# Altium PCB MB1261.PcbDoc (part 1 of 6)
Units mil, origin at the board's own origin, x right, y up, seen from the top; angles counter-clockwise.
Board outline 5119.1 x 2638.79 mil, 6 copper layers (TOP, L2_GND, L3_SIG, L4_VCC, L5_GND, BOTTOM), stack 61 mil thick; 336 components, 316 nets, 1358 pads, 871 vias.
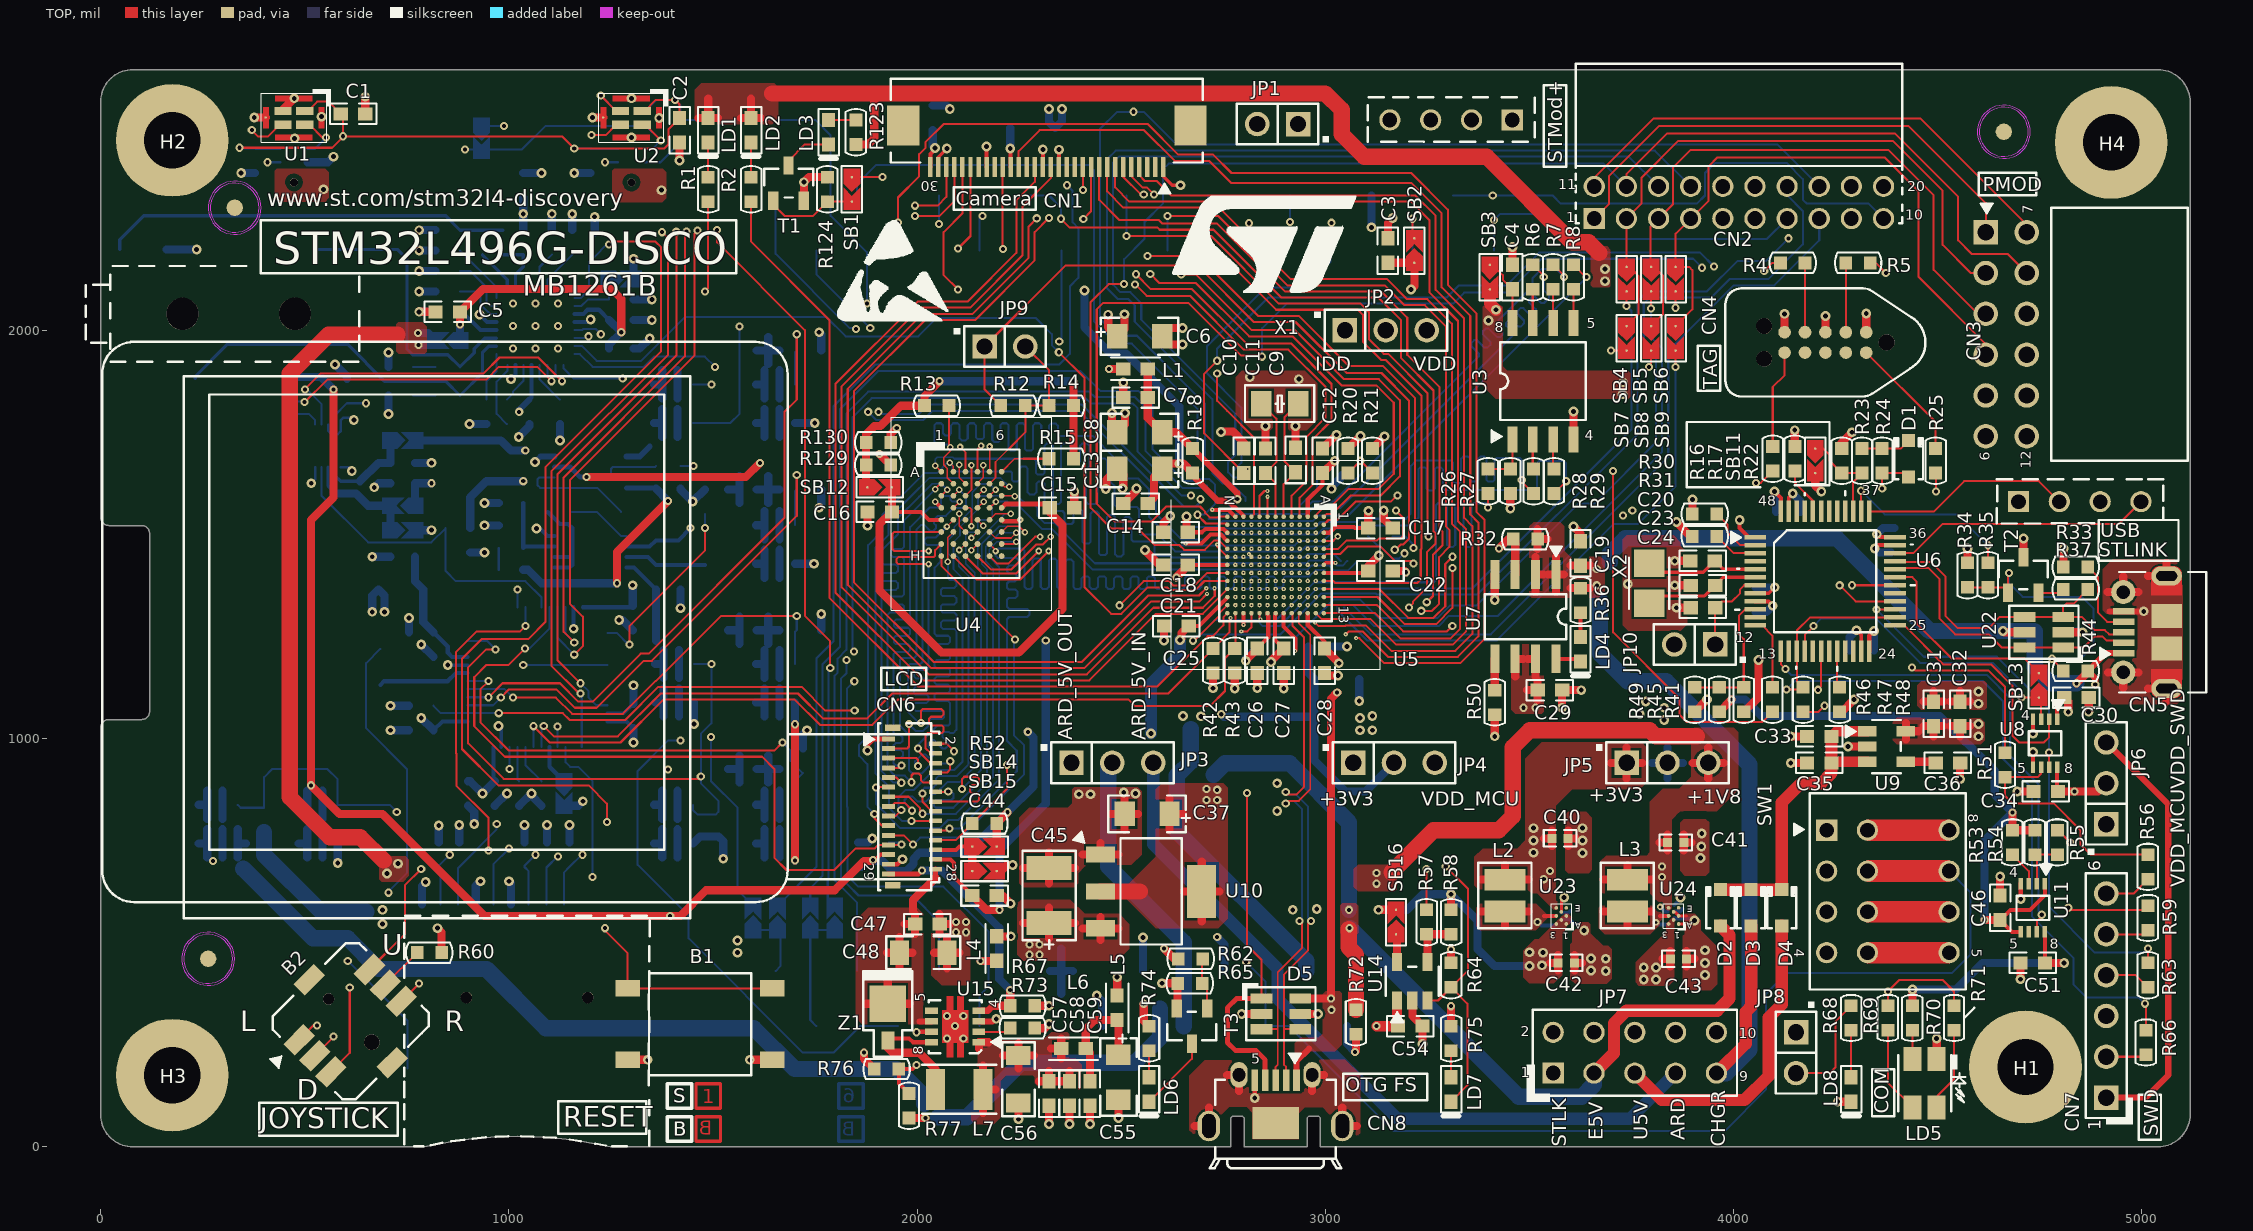
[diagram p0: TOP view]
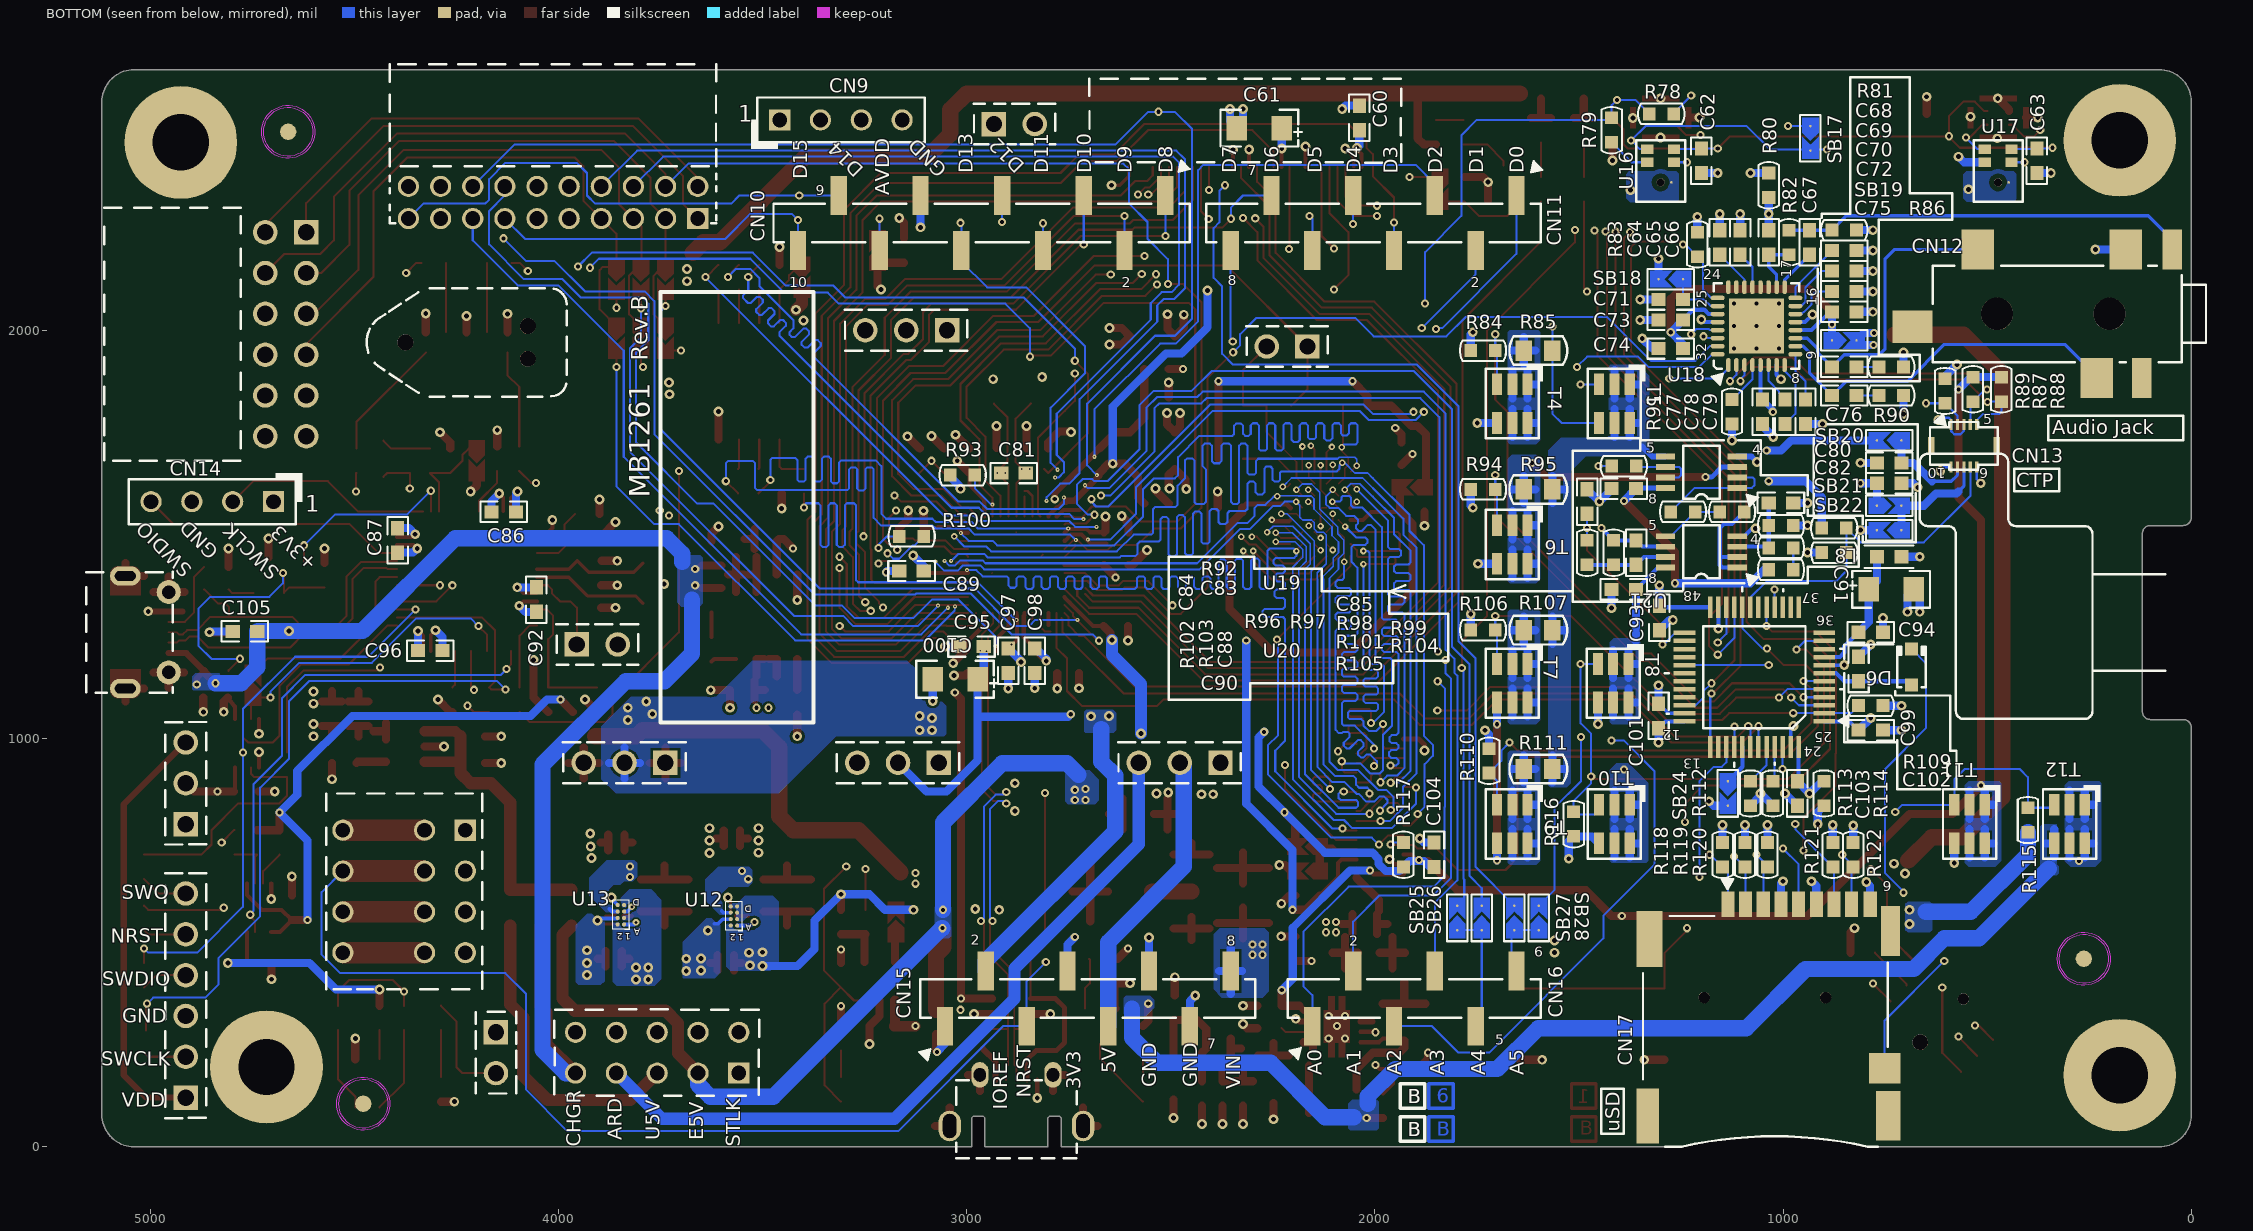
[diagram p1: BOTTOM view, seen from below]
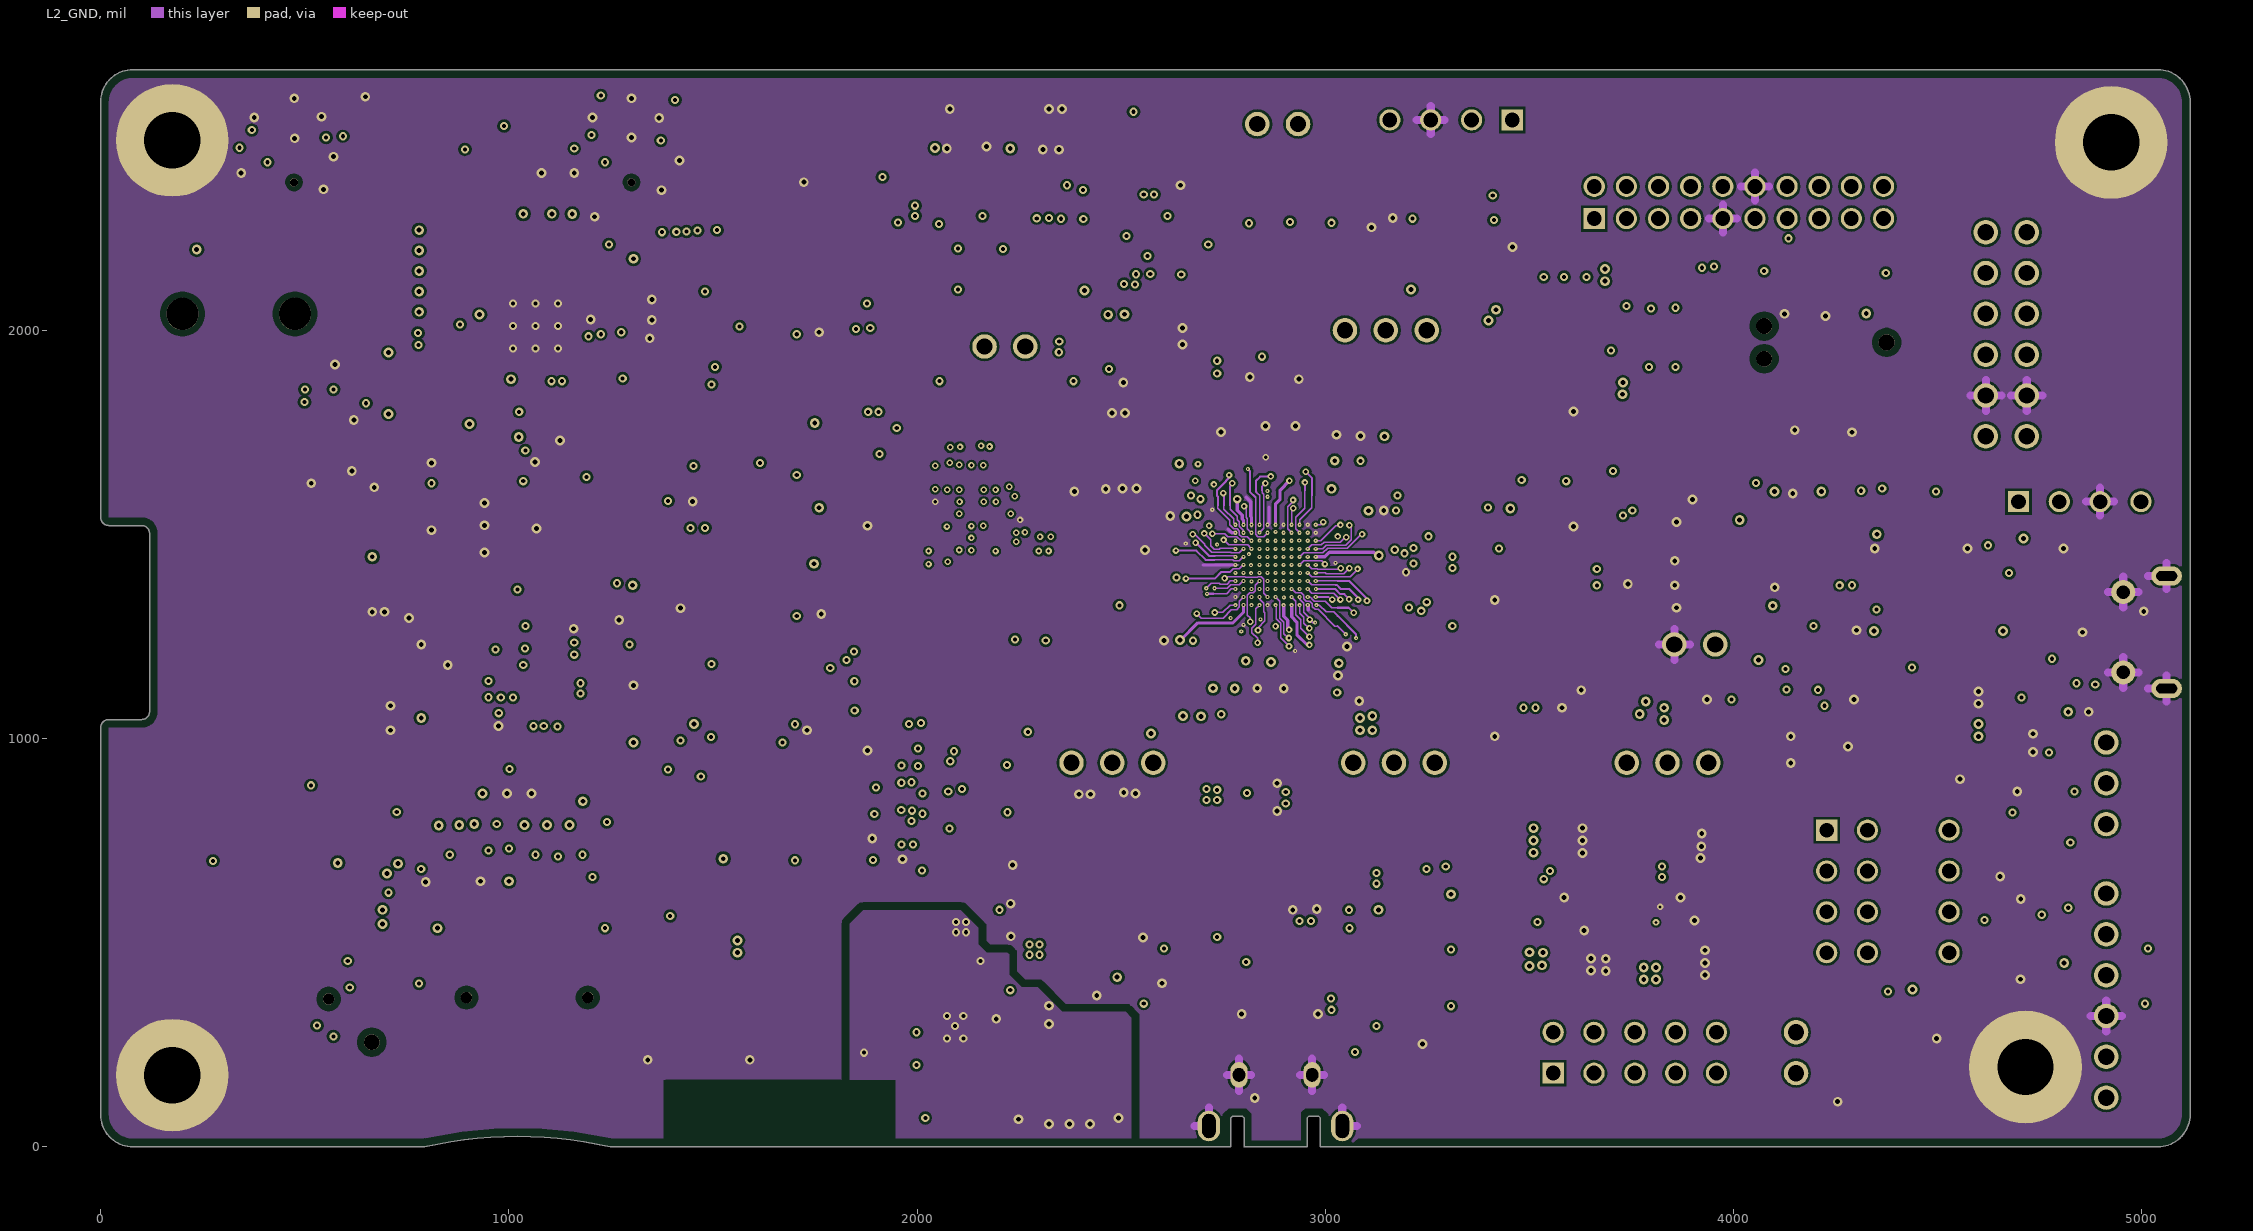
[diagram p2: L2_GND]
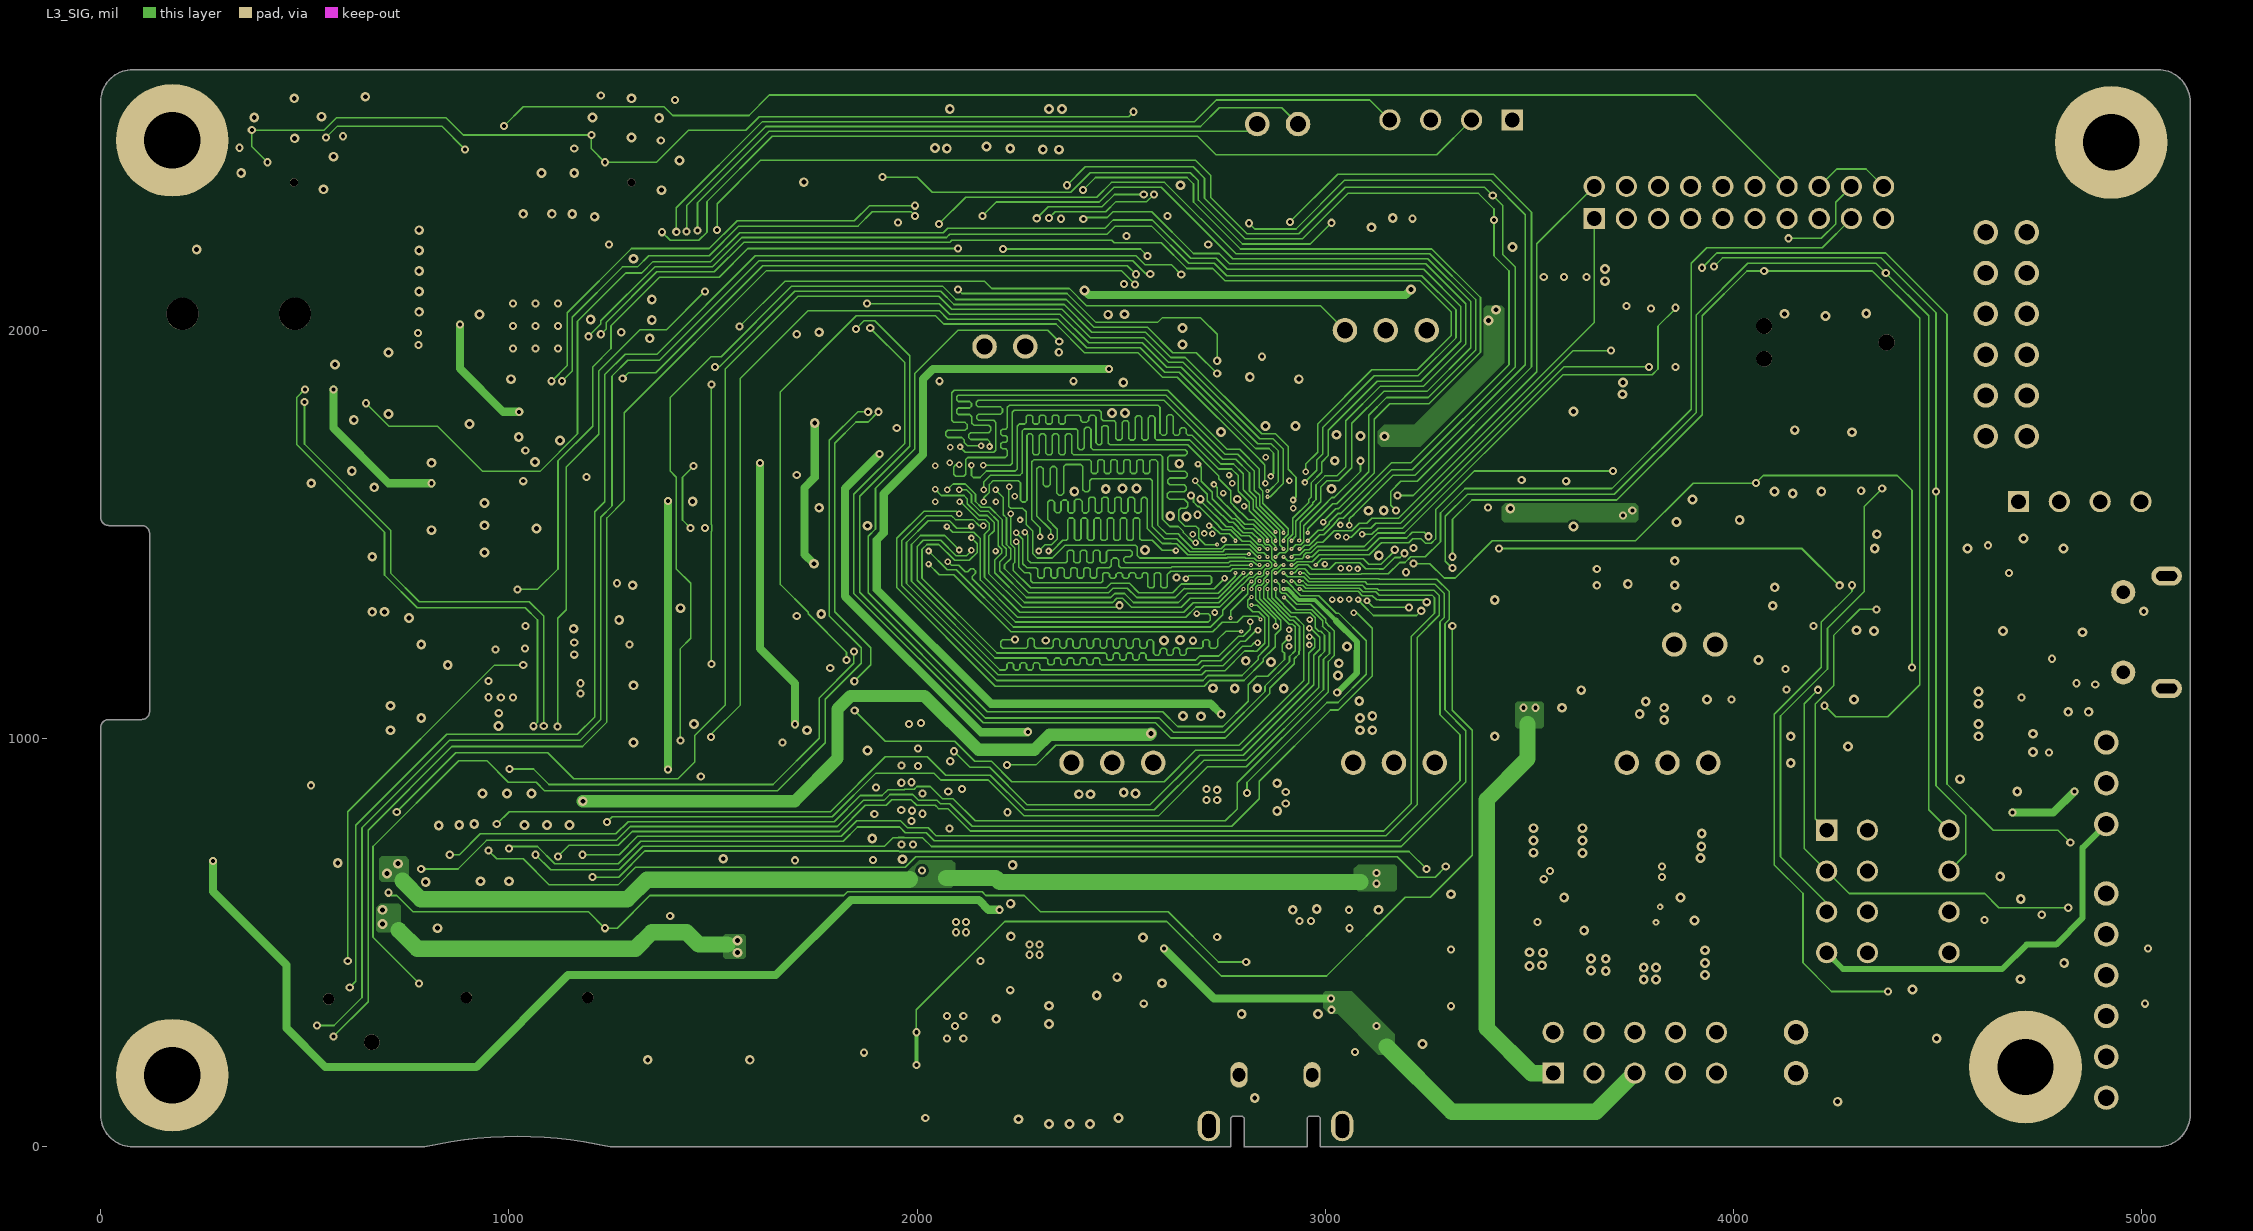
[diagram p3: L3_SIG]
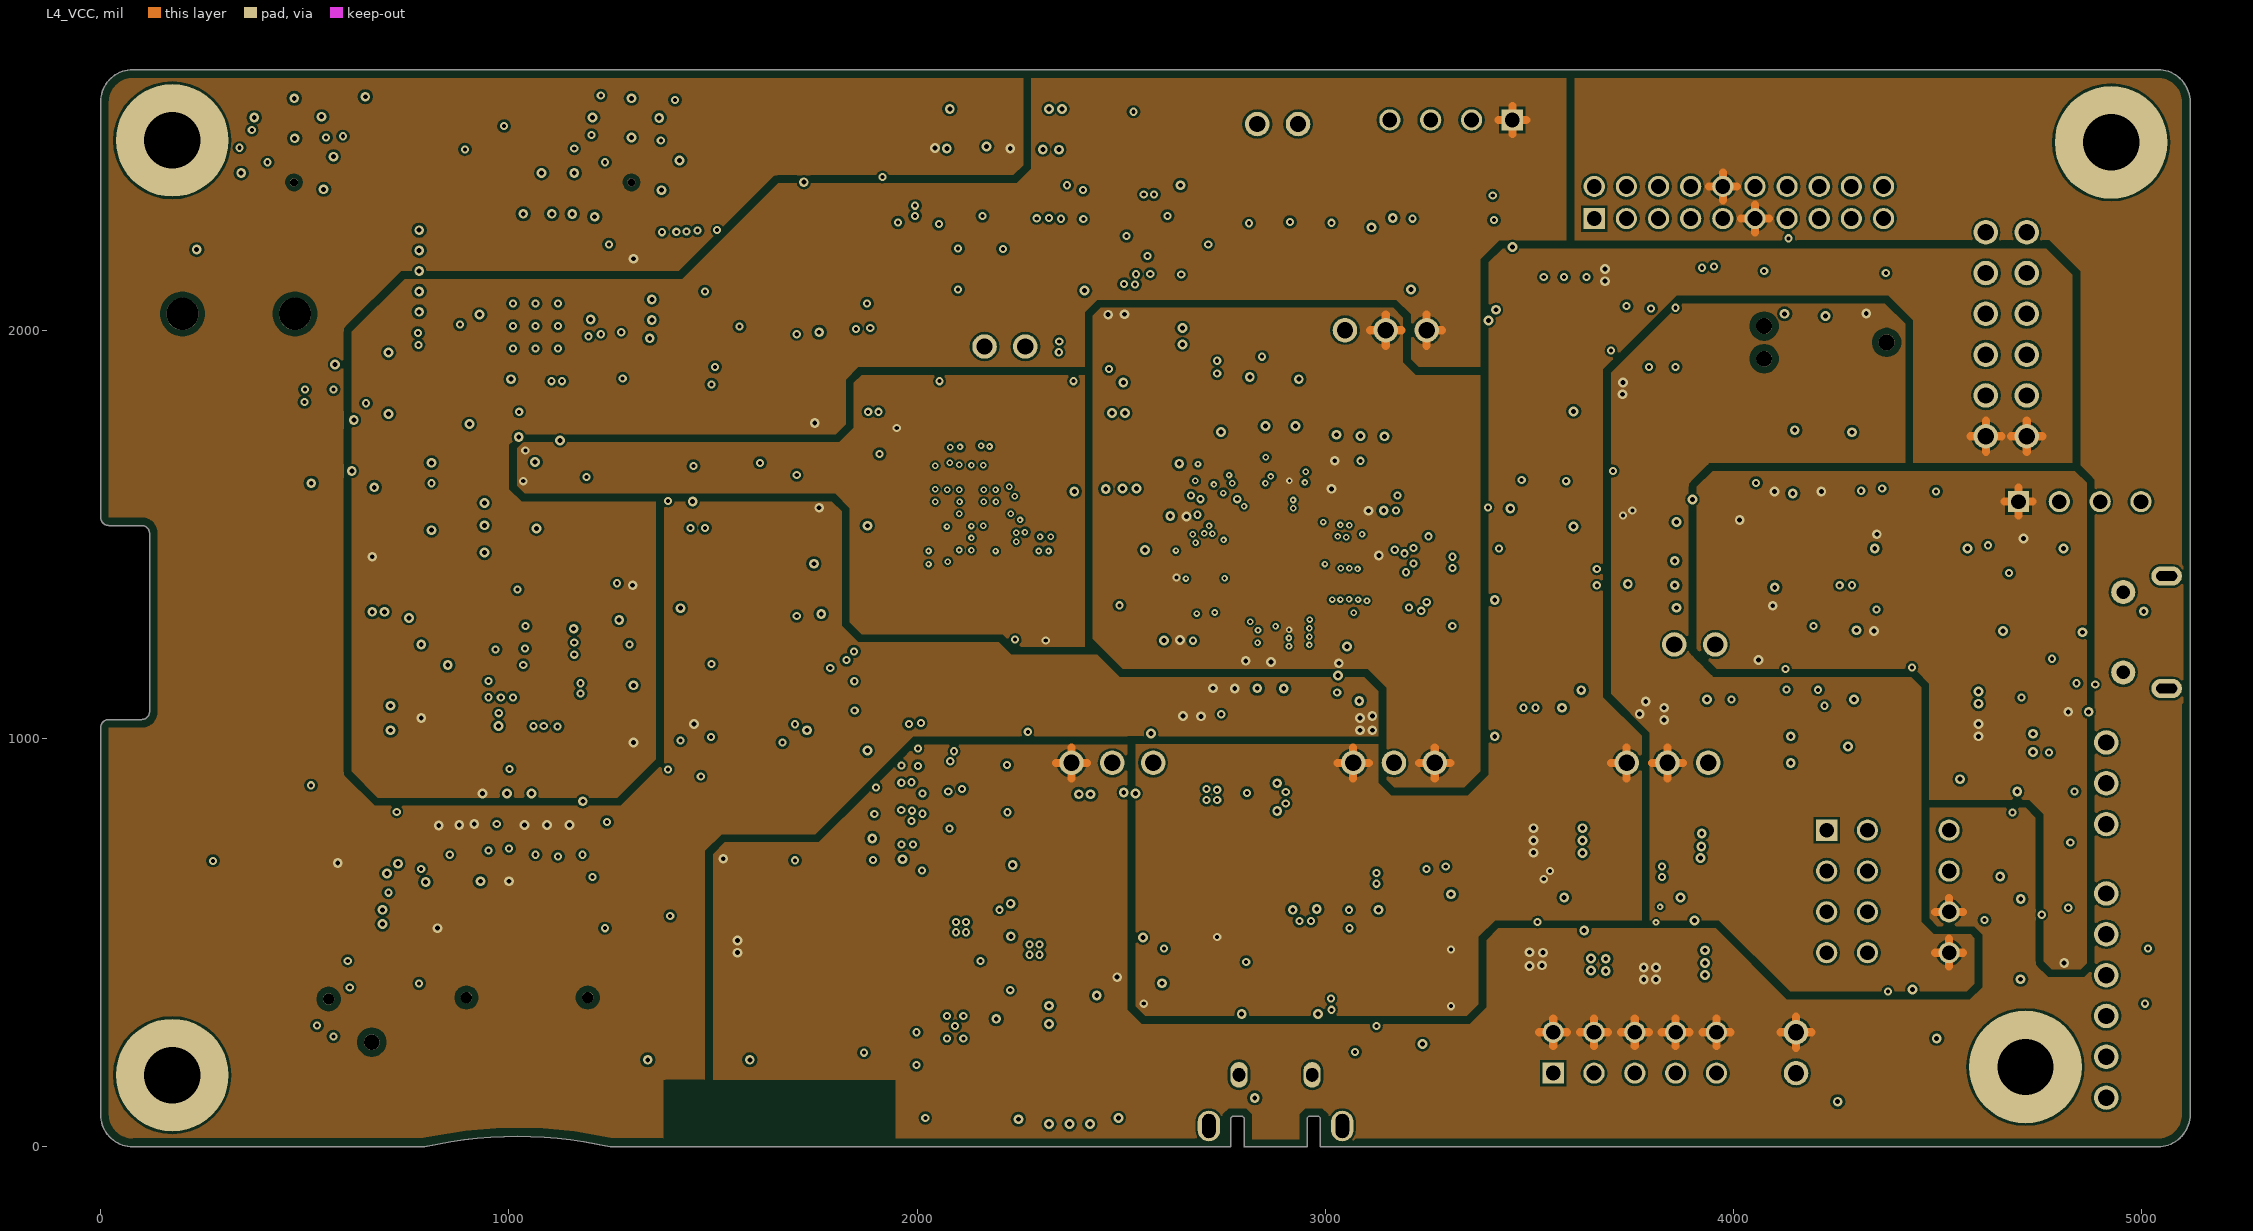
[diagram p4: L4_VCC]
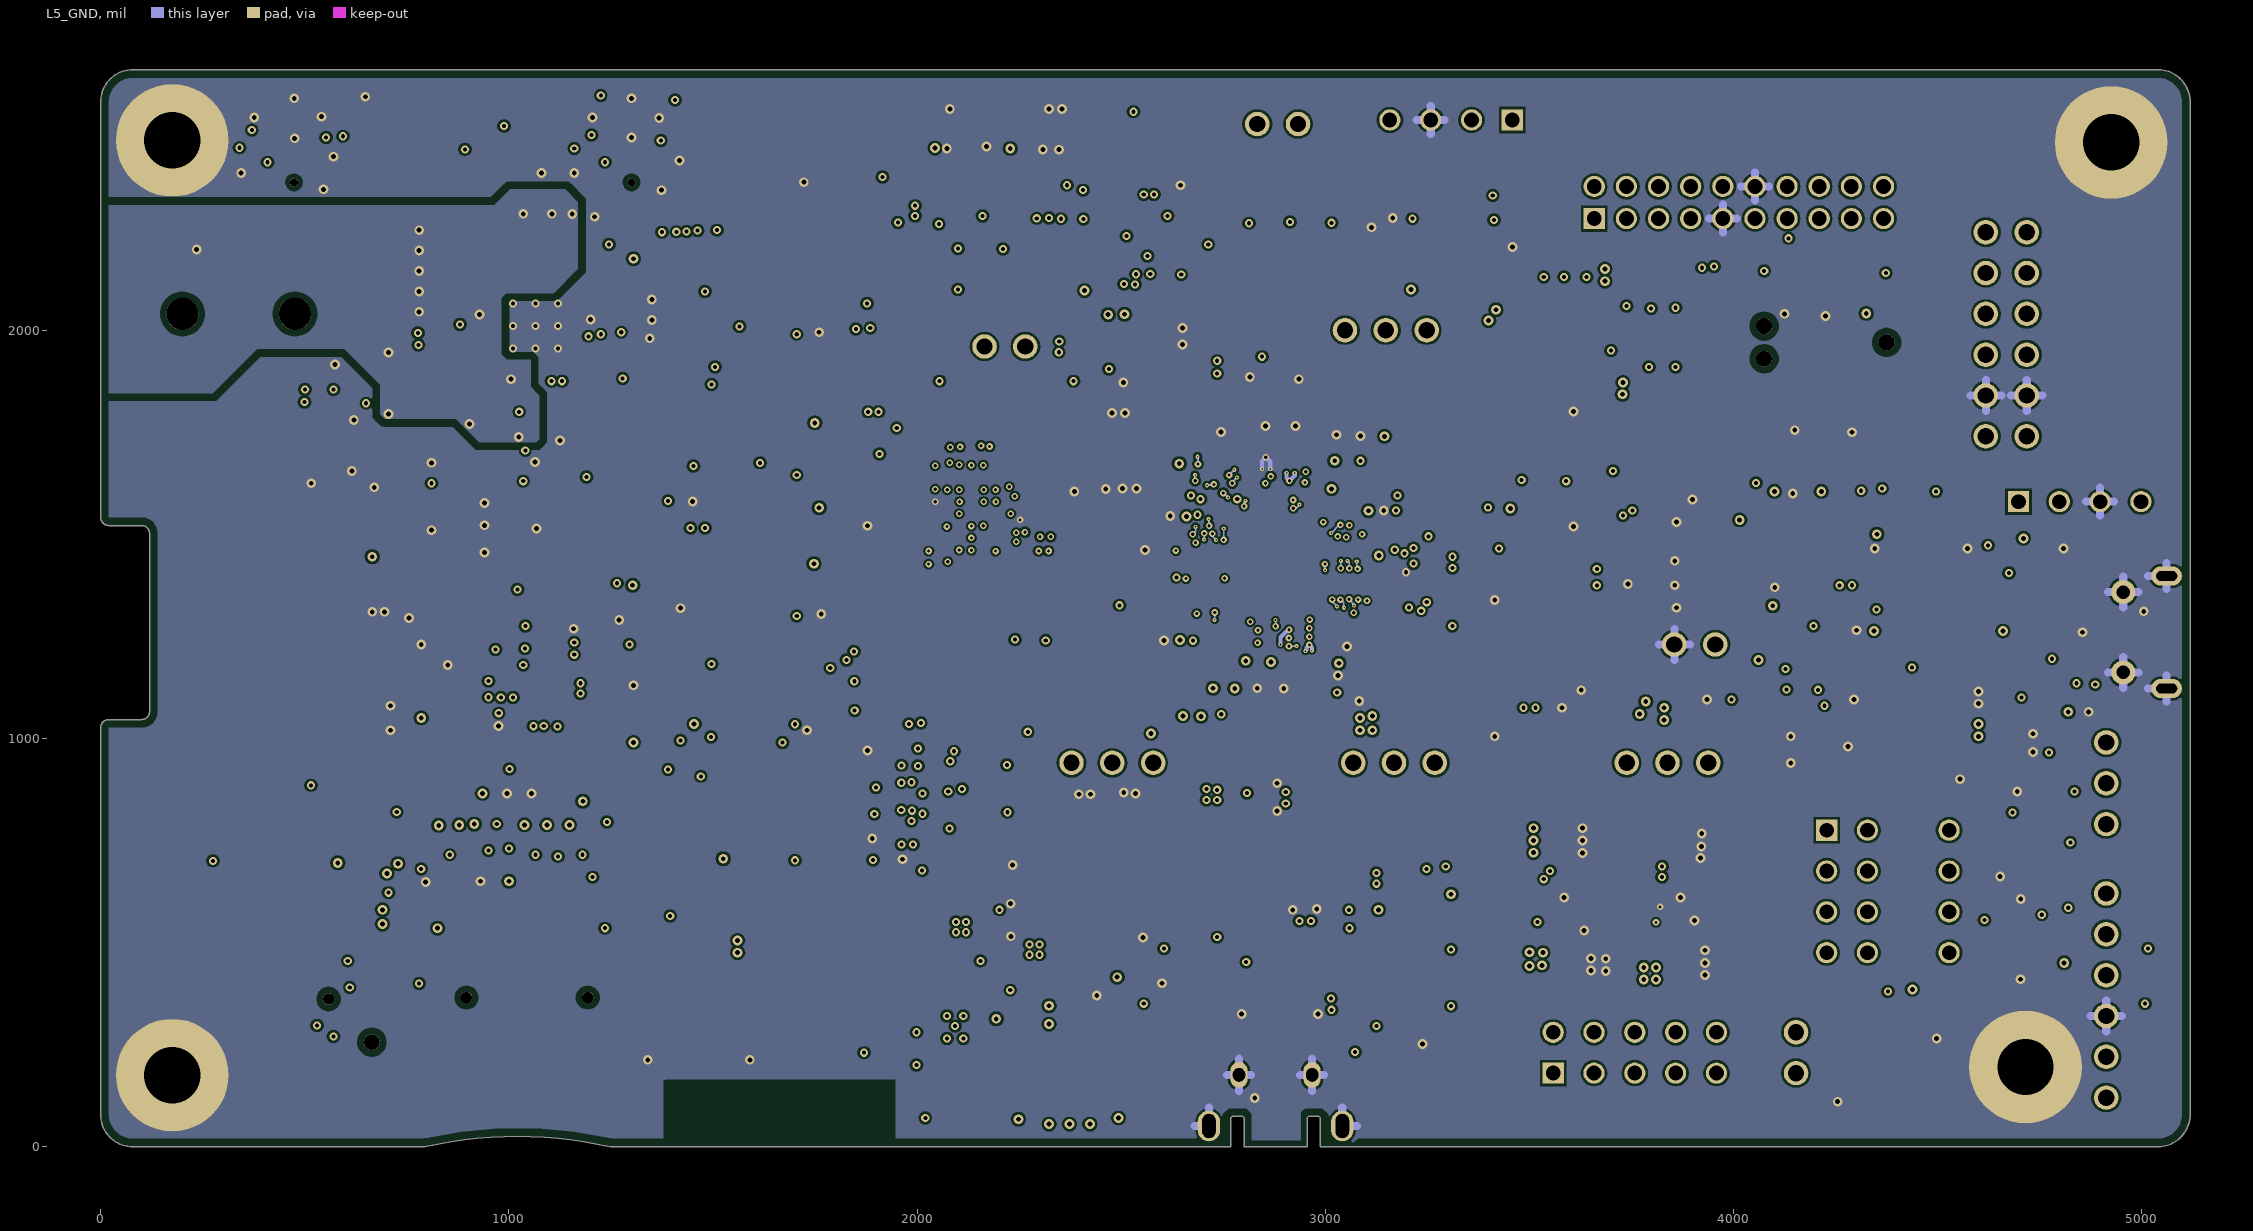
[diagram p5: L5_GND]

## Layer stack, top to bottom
Top Solder: solder mask 0.6, Solder Resist, Dk 3.5
TOP: signal copper 0.8
Dielectric 1: core 2.8, FR-4, Dk 4.3
L2_GND: signal copper 0.8
Dielectric2: core 4, FR-4, Dk 4.3
L3_SIG: signal copper 0.6
Dielectric3: core 43, FR-4, Dk 4.3
L4_VCC: signal copper 0.6
Dielectric4: core 4, FR-4, Dk 4.3
L5_GND: signal copper 0.8
Dielectric5: core 2.8, FR-4, Dk 4.3
BOTTOM: signal copper 0.8
Bottom Solder: solder mask 0.6, Solder Resist, Dk 3.5

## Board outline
-0.5,78.74 ccw(c78.74,78.74) 78.74,-0.5 793.1,-0.5 793.27,-0.47 cw(c1020.6,-1007.5) 1247.93,-0.47 1248.1,-0.5 2767.86,-0.5 2768.36,0 2768.36,70.07 2772.01,73.72 2797.18,73.72 2800.83,70.07 2800.83,0 2801.33,-0.5 2954.87,-0.5 2955.37,0 2955.37,70.07 2959.02,73.72 2984.19,73.72 2987.84,70.07 2987.84,0 2988.34,-0.5 5039.36,-0.5 ccw(c5039.36,78.74) 5118.6,78.74 5118.6,2559.05 ccw(c5039.36,2559.05) 5039.36,2638.29 78.74,2638.29 ccw(c78.74,2559.05) -0.5,2559.05 -0.5,1541.93 ccw(c20,1541.93) 20,1521.43 100,1521.43 cw(c100,1501.93) 119.5,1501.93 119.5,1065.71 cw(c100,1065.71) 100,1046.21 20,1046.21 ccw(c20,1025.71) -0.5,1025.71

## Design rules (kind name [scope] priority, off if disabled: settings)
Clearance Clearance_Chevron [HasFootprint('SB_0603')] p1: gap=6 ignorepadtopadclearanceinfootprint=TRUE except(0: Arc-Text Arc-Hole Track-Text Track-Hole SMDPad-Text SMDPad-Hole THPad-Text THPad-Hole Via-Text Via-Hole Fill-Text Fill-Hole Poly-Text Poly-Hole Region-Text Region-Hole Text-Text Text-Hole; 3: Fill-Fill Fill-Poly Fill-Region Poly-Poly Poly-Region Region-Region; 5: Arc-SMDPad Arc-THPad Arc-Via Track-SMDPad Track-THPad Track-Via SMDPad-SMDPad SMDPad-THPad SMDPad-Via THPad-THPad THPad-Via Via-Via; 10: Arc-Arc Arc-Track Track-Track)
Clearance Clearance_3mm_BBvia [WithinRoom('RoomDefinition_3MM')      or (ObjectKind = 'Via') And (AsMils(HoleDiameter) = 4) vs (ObjectKind = 'Via') And (AsMils(HoleDiameter) = 4)] p2: gap=0 ignorepadtopadclearanceinfootprint=FALSE except(3: Arc-Via Track-Via; 4: SMDPad-Via THPad-Via Via-Via; 5: Via-Fill Via-Poly Via-Region)
Clearance Clearance_3mm_BBvia_via [WithinRoom('RoomDefinition_3MM')      or isvia vs (ObjectKind = 'Via') And (AsMils(HoleDiameter) = 4)] p3: gap=0 ignorepadtopadclearanceinfootprint=FALSE except(3: Arc-Via Track-Via; 4: SMDPad-Via THPad-Via Via-Via; 5: Via-Fill Via-Poly Via-Region)
Clearance Clearance_3mm [TouchesRoom('RoomDefinition_3MM')] p4: gap=5 ignorepadtopadclearanceinfootprint=FALSE except(0: Arc-Text Track-Text SMDPad-Text THPad-Text Via-Text Fill-Text Poly-Text Region-Text Text-Text Text-Hole; 3: Arc-SMDPad Arc-THPad Arc-Via Track-SMDPad Track-THPad Track-Via SMDPad-Via THPad-Via Via-Via; 4: Arc-Arc Arc-Track Arc-Hole Track-Track Track-Hole Via-Hole; 15: Fill-Fill Fill-Poly Fill-Region Poly-Poly Poly-Region Region-Region)
Clearance Clearance_BGA [TouchesRoom('RoomDefinition_BGA1')  or TouchesRoom('RoomDefinition_BGA2')        or TouchesRoom('RoomDefinition_BGA3')    or TouchesRoom('RoomDefinition_BGA4')    or WithinRoom('RoomDefinition_BGA5')    or WithinRoom('RoomDefinition_BGA6')] p5: gap=5 ignorepadtopadclearanceinfootprint=FALSE except(0: Arc-Text Arc-Hole Track-Text Track-Hole SMDPad-Text SMDPad-Hole THPad-Text THPad-Hole Via-Text Via-Hole Fill-Text Fill-Hole Poly-Text Poly-Hole Region-Text Region-Hole Text-Text Text-Hole; 4: Arc-Arc Arc-Track Arc-SMDPad Arc-THPad Arc-Via Track-Track Track-SMDPad Track-THPad Track-Via SMDPad-Via THPad-Via; 15: Fill-Fill Fill-Poly Fill-Region Poly-Poly Poly-Region Region-Region)
Clearance Clearance_Default_L3_L4 [OnLayer('L3_SIG') or              OnLayer('L4_VCC')] p6: gap=6 ignorepadtopadclearanceinfootprint=FALSE except(0: Arc-Text Arc-Hole Track-Text Track-Hole SMDPad-Text SMDPad-Hole THPad-Text THPad-Hole Via-Text Via-Hole Fill-Text Fill-Hole Poly-Text Poly-Hole Region-Text Region-Hole Text-Text Text-Hole; 5: Arc-SMDPad Arc-THPad Arc-Via Track-SMDPad Track-THPad Track-Via SMDPad-SMDPad SMDPad-THPad SMDPad-Via THPad-THPad THPad-Via Via-Via; 8: Arc-Arc Arc-Track Track-Track; 20: Fill-Fill Fill-Poly Fill-Region Poly-Poly Poly-Region Region-Region)
Clearance Clearance_Default [All] p7: gap=6 ignorepadtopadclearanceinfootprint=FALSE except(0: Arc-Text Track-Text SMDPad-Text THPad-Text Via-Text Fill-Text Poly-Text Region-Text Text-Text Text-Hole; 5: Arc-SMDPad Arc-THPad Arc-Via Arc-Hole Track-SMDPad Track-THPad Track-Via Track-Hole SMDPad-SMDPad SMDPad-THPad SMDPad-Via SMDPad-Hole THPad-THPad THPad-Via THPad-Hole Via-Via Via-Hole; 10: Arc-Arc Arc-Track Track-Track; 20: Fill-Fill Fill-Poly Fill-Region Poly-Poly Poly-Region Region-Region)
ComponentClearance [All] p1: gap=0 collisioncheckmode=3 verticalgap=0 showdistances=FALSE
DiffPairsRouting [InDifferentialPairClass('90Ohms')] p1: maxlimit=10.2 minlimit=9.5 mostfreqgap=10.2 toplayer_mingap=10.2 toplayer_minwidth=4.8 toplayer_maxwidth=4.8 toplayer_prefwidth=4.8 midlayer1_mingap=10.2 midlayer1_minwidth=4.8 midlayer1_maxwidth=4.8 midlayer1_prefwidth=4.8 midlayer2_maxgap=9.5 midlayer2_prefgap=9.5 midlayer2_minwidth=5.5 midlayer2_maxwidth=5.5 midlayer2_prefwidth=5.5 midlayer3_maxgap=9.5 midlayer3_prefgap=9.5 midlayer3_minwidth=5.5 midlayer3_maxwidth=5.5 midlayer3_prefwidth=5.5 midlayer4_mingap=10.2 midlayer4_minwidth=4.8 midlayer4_maxwidth=4.8 midlayer4_prefwidth=4.8 bottomlayer_mingap=10.2 bottomlayer_minwidth=4.8 bottomlayer_maxwidth=4.8 bottomlayer_prefwidth=4.8 maxuncoupledlength=500
HoleSize [All] p1: absolutevalues=TRUE maxlimit=140 minlimit=1 maxpercent=80.000 minpercent=20.000
HoleToHoleClearance [All] p1: gap=5 allowstackedmicrovias=TRUE
PlaneConnect PlaneConnect_BGA8 [(ObjectKind = 'Component') And (Footprint = 'BGA8_0R312-0R25_1R11X1R41')] p1: planeconnectstyle=Direct reliefexpansion=20 reliefentries=4 reliefconductorwidth=10 reliefairgap=10
PlaneConnect [All] p2: planeconnectstyle=Relief reliefexpansion=20 reliefentries=4 reliefconductorwidth=10 reliefairgap=10
PolygonConnect PolygonConnect_Hole [(Component = 'H4') or (Component = 'H3') or (Component = 'H2')or (Component = 'H1')] p1: connectstyle=Direct reliefconductorwidth=10 reliefentries=4 polygonreliefangle="90 Angle" airgapwidth=10
PolygonConnect PolygonConnect_USB [(ObjectKind = 'Pad') And (Layer = 'TOP') And (Name = 'CN5-10') or  (ObjectKind = 'Pad') And (Layer = 'TOP') And (Name = 'CN5-11') or (ObjectKind = 'Pad') And (Layer = 'TOP') And (Name = 'CN8-10')] p2: connectstyle=Direct reliefconductorwidth=10 reliefentries=4 polygonreliefangle="90 Angle" airgapwidth=10
PolygonConnect PolygonConnect_U17-U16 [(ObjectKind = 'Pad') And (Name = 'U17-3') or (ObjectKind = 'Pad') And (Name = 'U16-3')] p3: connectstyle=Direct reliefconductorwidth=10 reliefentries=4 polygonreliefangle="90 Angle" airgapwidth=10
PolygonConnect PolygonConnect_via [IsVia] p4: connectstyle=Direct reliefconductorwidth=10 reliefentries=4 polygonreliefangle="90 Angle" airgapwidth=10
PolygonConnect PolygonConnect_bga8 [(ObjectKind = 'Pad') And (Component = 'U23')or (Component = 'U24')or (Component = 'U12')or (Component = 'U13')] p5: connectstyle=Direct reliefconductorwidth=10 reliefentries=4 polygonreliefangle="90 Angle" airgapwidth=10
PolygonConnect [All] p6: connectstyle=Relief reliefconductorwidth=10 reliefentries=4 polygonreliefangle="90 Angle" airgapwidth=6
RoomDefinition Power [InComponentClass('Power')] p1: confinementstyle=ConfineIn formatcopy=TRUE lockcomponents=FALSE outline 4918.63,1185 4967.03,1185 4967.03,1241.2 4918.63,1241.2
RoomDefinition PSRAM [InComponentClass('PSRAM')] p2: confinementstyle=ConfineIn formatcopy=TRUE lockcomponents=FALSE outline 4384,1384 4444,1384 4444,1474 4384,1474
RoomDefinition QSPI [InComponentClass('QSPI')] p3: confinementstyle=ConfineIn formatcopy=TRUE lockcomponents=FALSE outline 3780,565 3780,610 3790,620 3805,620 3820,605 3878,605 3878,535.3 3809.7,535.3
RoutingVias [All] p1: holewidth=12 width=24 viastyle="Through Hole" minholewidth=4 minwidth=10 maxholewidth=12 maxwidth=24
ShortCircuit [(ObjectKind = 'Pad') And (Component = 'SW1')] p1: allowed=TRUE
SolderMaskExpansion [All] p1: expansion=3 istentingtop=FALSE
Width Width_20 [InNetClass('20MIL')] p1: maxlimit=100 minlimit=5 preferedwidth=20 minimp=50.000000 maximp=50.000000 favimp=50.000000
Width Width_3mm [TouchesRoom('RoomDefinition_3MM')] p2: maxlimit=100 minlimit=3.5 preferedwidth=3.5 minimp=50.000000 maximp=50.000000 favimp=50.000000
Width Width_BGA [WithinRoom('RoomDefinition_BGA1') or   WithinRoom('RoomDefinition_BGA2') or             WithinRoom('RoomDefinition_BGA3') or     WithinRoom('RoomDefinition_BGA4') or      WithinRoom('RoomDefinition_BGA5') or          WithinRoom('RoomDefinition_BGA6') or   WithinRoom('RoomDefinition_BGA7')] p3: maxlimit=12 minlimit=4 preferedwidth=4 midlayer1_maxwidth=10 midlayer2_maxwidth=10 midlayer3_maxwidth=10 midlayer4_maxwidth=10 bottomlayer_maxwidth=10 minimp=50.000000 maximp=50.000000 favimp=50.000000
Width [All] p4: maxlimit=100 minlimit=4 preferedwidth=4 toplayer_minwidth=5 toplayer_prefwidth=5 bottomlayer_minwidth=5 bottomlayer_prefwidth=5 minimp=60.000000 maximp=60.000000 favimp=60.000000
24 further rules are at their usual default settings.

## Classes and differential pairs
component class U_Top: H1 H2 H3 H4
component class TFT_LCD: C44 C47 C48 C55 C56 C57 C58 C59 C80 C82 C104 CN6 CN13 L4 L5 L6 L7 R52 R67 R73 R76 R77 R87 R88 R89 R99 R104 R115 R117 SB14 SB15 SB20 SB21 SB22 T11 T12 U15 Z1 ZZ1
component class STMOD+: CN2 CN3 SB4 SB5 SB6 SB7 SB8 SB9
component class ST_LINK: C19 C20 C23 C24 C29 C30 C31 C32 C33 C34 C35 C36 C46 C51 C86 C87 C92 C96 C105 CN4 CN5 CN7 CN14 D1 D2 D3 D4 JP6 JP10 LD4 LD5 R4 R5 R16 R17 R22 R23 R24 R25 R30 R31 R32 R33 R34 R35 R36 R37 R41 R44 R45 R46 R47 R48 R49 R50 R51 R53 R54 R55 R56 R59 R63 R66 R69 R70 R71 SB11 SB13 SW1 T2 U6 U7 U8 U9 U11 U22 X2
component class QSPI: C4 R6 R7 R8 R26 R27 R28 R29 SB3 U3
component class PSRAM: C15 C16 JP9 R12 R13 R14 R15 R129 R130 SB12 U4
component class Power: C37 C40 C41 C42 C43 C45 JP3 JP5 JP7 JP8 L2 L3 LD8 R68 U10 U12 U13 U23 U24
component class Peripherals: B1 B2 CN17 LD1 LD2 R1 R2 R60 R118 R119 R120 R121 R122
component class OTG: C54 CN8 D5 LD6 LD7 R57 R58 R62 R64 R65 R74 R75 SB16 T3 U14
component class MCU: C6 C7 C8 C9 C10 C11 C12 C13 C14 C17 C18 C21 C22 C25 C26 C27 C28 C81 C89 C95 C97 C98 C100 JP4 L1 R18 R20 R21 R42 R43 R93 U5 X1
component class IDD: C83 C84 C85 C88 C90 C91 C93 C94 C99 C101 C102 C103 CN9 D6 JP1 JP2 L8 R84 R85 R92 R94 R95 R96 R97 R98 R101 R102 R103 R105 R106 R107 R109 R110 R111 R112 R113 R114 R116 SB24 T4 T5 T6 T7 T8 T9 T10 U19 U20 U21
component class "Camera Interface": C60 C61 CN1 R100
component class Audio: C1 C2 C5 C62 C63 C64 C65 C66 C67 C68 C69 C70 C71 C72 C73 C74 C75 C76 C77 C78 C79 CN12 R78 R79 R80 R81 R82 R83 R86 R90 R91 SB17 SB18 SB19 U1 U2 U16 U17 U18
component class "Arduino_ Connectors": C3 CN10 CN11 CN15 CN16 LD3 R72 R123 R124 SB1 SB2 SB25 SB26 SB27 SB28 T1
net class PSRAM_A[0..18]: PSRAM_A0 PSRAM_A1 PSRAM_A2 PSRAM_A3 PSRAM_A4 PSRAM_A5 PSRAM_A6 PSRAM_A7 PSRAM_A8 PSRAM_A9 PSRAM_A10 PSRAM_A11 PSRAM_A12 PSRAM_A13 PSRAM_A14 PSRAM_A15 PSRAM_A16 PSRAM_A17 PSRAM_A18
net class D[0..15]: D0 D1 D2 D3 D4 D5 D6 D7 D8 D9 D10 D11 D12 D13 D14 D15
net class DCMI_D[0..7]: DCMI_D0 DCMI_D1 DCMI_D2 DCMI_D3 DCMI_D4 DCMI_D5 DCMI_D6 DCMI_D7
differential pair D_: +D_P -D_N

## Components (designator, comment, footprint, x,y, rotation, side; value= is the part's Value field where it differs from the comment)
B1 "TD-0341X-A00" PB10 1468.11,300 r180 top
B2 "MT008-A" MT-008A 614.56,306.78 r315 top
C1 "CC0603KRX7R7BB104" 0603C 618.1,2530 r0 top value=100nF
C2 "CC0603KRX7R7BB104" 0603C 1418.1,2490 r270 top value=100nF
C3 "" 0603C 3153.1,2195 r90 top value=100nF
C4 "CC0603KRX7R7BB104" 0603C 3458.1,2130 r90 top value=100nF
C5 "CC0603KRX7R7BB104" 0603C 850,2045 r180 top value=100nF
C6 "TAJA475K016R" TAN-A 2545,1985 r180 top value=4.7uF
C7 "CC0603KRX7R7BB104" 0603C 2535,1835 r180 top value=100nF
C8 "TAJA105K016R" TAN-A 2545,1750 r0 top value=1uF
C9 "5.6pF" 0603C 2927.1,1682 r270 top
C10 "CC0603KRX7R7BB104" 0603C 2800,1680 r90 top value=100nF
C11 "5.6pF" 0603C 2853.1,1680 r270 top
C12 "CC0603KRX7R7BB104" 0603C 2993.1,1680 r90 top value=100nF
C13 "TAJA105K016R" TAN-A 2545,1660 r0 top value=1uF
C14 "CC0603KRX7R7BB104" 0603C 2535,1575 r180 top value=100nF
C15 "CC0603KRX7R7BB104" 0603C 2355,1565 r0 top value=100nF
C16 "CC0603KRX7R7BB104" 0603C 1908.1,1555 r180 top value=100nF
C17 "CC0603KRX7R7BB104" 0603C 3135,1515 r0 top value=100nF
C18 "CC0603KRX7R7BB104" 0603C 2633.1,1505 r180 top value=100nF
C19 "CC0603KRX5R7BB105" 0603C 3625,1453.1 r270 top value=1uF
C20 "CC0603JRNPO9BN100" 0603C 3924.1,1435 r0 top value=10pF
C21 "CC0603KRX7R7BB104" 0603C 2633.1,1425 r180 top value=100nF
C22 "CC0603KRX7R7BB104" 0603C 3135,1410 r0 top value=100nF
C23 "CC0603JRNPO9BN100" 0603C 3925,1375 r0 top value=10pF
C24 "CC0603KRX7R7BB104" 0603C 3925,1320 r180 top value=100nF
C25 "CC0603KRX7R7BB104" 0603C 2635,1275 r180 top value=100nF
C26 "CC0603KRX7R7BB104" 0603C 2833.1,1190 r270 top value=100nF
C27 "CC0603KRX7R7BB104" 0603C 2898.1,1190 r270 top value=100nF
C28 "CC0603KRX7R7BB104" 0603C 2998.1,1190 r270 top value=100nF
C29 "CC0603KRX7R7BB104" 0603C 3550,1118.1 r180 top value=100nF
C30 "CC0603KRX7R7BB104" 0603C 4840,1100 r180 top value=100nF
C31 "CC0603KRX7R7BB104" 0603C 4490,1060 r90 top value=100nF
C32 "CC0603KRX5R7BB105" 0603C 4555,1060 r90 top value=1uF
C33 "CC0603KRX7R7BB104" 0603C 4210,1005 r180 top value=100nF
C34 "CC0603KRX7R7BB104" 0603C 4765,870 r180 top value=100nF
C35 "CC0603KRX5R7BB105" 0603C 4210,940 r180 top value=1uF
C36 "CC0603KRX7R9BB103" 0603C 4525,940 r0 top value=10nF
C37 "TAJA106K016R" TAN-A 2563.1,815 r0 top value=10uF
C40 "GRM155R60J106ME11" 0402C 3575,755 r0 top value=10uF
C41 "GRM155R60J106ME11" 0402C 3858.1,745 r0 top value=10uF
C42 "GRM155R60J106ME11" 0402C 3590,450 r0 top value=10uF
C43 "GRM155R60J106ME11" 0402C 3865,460 r0 top value=10uF
C44 "CC0603KRX7R7BB104" 0603C 2165,615 r0 top value=100nF
C45 "TAJB106K025RNJ" TAN-B 2323.1,615 r90 top value=10uF
C46 "CC0603KRX7R7BB104" 0603C 4653.1,585 r90 top value=100nF
C47 "CC0603KRX7R9BB103" 0603C 2025,545 r0 top value=10nF
C48 "CC1206KKX7R9BB475" 1206C 2015,475 r0 top value=4.7uF
C51 "CC0603KRX7R7BB104" 0603C 4733.1,450 r0 top value=100nF
C54 "CC0603KRX5R7BB475" 0603C 3208.1,295 r0 top value=4.7uF
C55 "TAJA106K016R" TAN-A 2493.1,170 r90 top value=10uF
C56 "C1206X475K8NAC" 1206C 2248.1,165 r270 top value=4.7uF
C57 "CC0603KRX7R9BB103" 0603C 2323.1,130 r270 top value=10nF
C58 "CC0603KRX7R7BB104" 0603C 2373.1,130 r270 top value=100nF
C59 "CC0603KRX7R7BB104" 0603C 2423.1,130 r270 top value=100nF
C60 "CC0603KRX7R7BB104" 0603C 2038.1,2520 r90 bottom value=100nF
C61 "TAJA106K016R" TAN-A 2283.1,2495 r180 bottom value=10uF
C62 "" 0603C 1200,2415 r270 bottom value=100nF
C63 "" 0603C 378.1,2415 r270 bottom value=100nF
C64 "CC0603JRNPO9BN151" 0603C 1155,2215 r90 bottom value=150pF
C65 "CC0603JRNPO9BN151" 0603C 1105,2215 r90 bottom value=150pF
C66 "CC0603KRX7R7BB104" 0603C 1035,2215 r270 bottom value=100nF
C67 "CC0603KRX5R7BB105" 0603C 935,2215 r270 bottom value=1uF
C68 "C1608X5R1A106K080AC" 0603C 850,2195 r0 bottom value=10uF
C69 "CC0603KRX5R7BB105" 0603C 850,2145 r0 bottom value=1uF
C70 "CC0603KRX5R7BB105" 0603C 850,2095 r0 bottom value=1uF
C71 "CC0603KRX7R7BB104" 0603C 1275,2075 r180 bottom value=100nF
C72 "CC0603KRX7R7BB104" 0603C 850,2045 r180 bottom value=100nF
C73 "CC0603KRX7R7BB104" 0603C 1275,2025 r0 bottom value=100nF
C74 "CC0603KRX5R7BB105" 0603C 1275,1955 r0 bottom value=1uF
C75 "CC0603KRX7R8BB223" 0603C 850,1910 r180 bottom value=22nF
C76 "CC0603KRX7R8BB223" 0603C 850,1840 r180 bottom value=22nF
C77 "CC0603KRX5R7BB105" 0603C 1050,1800 r270 bottom value=1uF
C78 "CC0603KRX5R7BB105" 0603C 995,1800 r90 bottom value=1uF
C79 "CC0603KRX5R7BB105" 0603C 945,1800 r90 bottom value=1uF
C80 "CC0603KRX7R7BB104" 0603C 740,1675 r0 bottom value=100nF
C81 "CC0603KRX7R7BB104" 0603C 2885,1650 r180 bottom value=100nF
C82 "CC0603KRX7R7BB104" 0603C 740,1625 r180 bottom value=100nF
C83 "CC0603KRX7R7BB104" 0603C 1390,1611.9 r180 bottom value=100nF
C84 "CC0603KRX5R7BB105" 0603C 1480,1580 r90 bottom value=1uF
C85 "CC0603KRX7R7BB104" 0603C 1005,1576.9 r0 bottom value=100nF
C86 "CC0603KRX7R7BB104" 0603C 4134.1,1555 r0 bottom value=100nF
C87 "CC0603KRX7R7BB104" 0603C 4394.1,1485 r270 bottom value=100nF
C88 "CC0603KRX7R7BB104" 0603C 1360,1455 r270 bottom value=100nF
C89 "CC0603KRX7R7BB104" 0603C 3135,1410 r0 bottom value=100nF
C90 "CC0603KRX7R7BB104" 0603C 1390,1365 r0 bottom value=100nF
C91 "TAJA105K016R" TAN-A 735,1365 r0 bottom value=1uF
C92 "CC0603KRX7R7BB104" 0603C 4054.1,1340 r90 bottom value=100nF
C93 "CC0603KRX7R7BB104" 0603C 1303.1,1295 r270 bottom value=100nF
C94 "CC0603KRX7R7BB104" 0603C 785,1260 r180 bottom value=100nF
C95 "CC0603KRX7R7BB104" 0603C 2988.1,1225 r0 bottom value=100nF
C96 "CC0603KRX7R7BB104" 0603C 4314.1,1215 r180 bottom value=100nF
C97 "CC0603KRX7R7BB104" 0603C 2898.1,1190 r270 bottom value=100nF
C98 "CC0603KRX7R7BB104" 0603C 2833.1,1190 r270 bottom value=100nF
C99 "" 0603C 815,1170 r270 bottom value=100nF
C100 "TAJA105K016R" TAN-A 3028.1,1145 r180 bottom value=1uF
C101 "CC0603KRX7R7BB104" 0603C 1305,1055 r90 bottom value=100nF
C102 "CC0603KRX7R7BB104" 0603C 785,1020 r180 bottom value=100nF
C103 "CC0603KRX7R7BB104" 0603C 965,865 r270 bottom value=100nF
C104 "CC0603KRX7R7BB104" 0603C 1855,715 r90 bottom value=100nF
C105 "CC0603KRX7R7BB104" 0603C 4768,1262 r0 bottom value=100nF
CN1 "FPU330ZH-BT1D3-CA" FPU330ZH-BT1D3-CA 2318.1,2492.5 r180 top
CN2 "SQT-110-01-F-D-RA" SQT-110-01-F-D-RA 4018.04,2448.42 r180 top
CN3 "SSW-106-02-F-D-RA" SSW-106-02-F-D-RA 4847.6,1990 r90 top
CN4 "Tag-10_C" TC2050-IDC-NL 4224.8,1970 r180 top
CN5 "1050170001" MICRO_USB_B_105017 5041.15,1260 r90 top
CN6 "FH26W-29S-0.3SHW(60)" FH26-29S-0R3SHW 1989.85,834.63 r270 top
CN7 "313106S111116" HDR_1X6_2R54_W 4913.1,370 r90 top
CN8 "475900001" MOLEX_47590001 2878.1,77.74 r0 top
CN9 "" HDR_1X4_2R54 3308.1,2515 r0 bottom
CN10 "SSW-110-22-X-S-VS" SSW-110-22-X-S-VS 2963.1,2262.5 r180 bottom value="Socket 10x1"
CN11 "SSW-108-22-L-S-VS" SSW-108-22-X-S-VS 2003.1,2262.5 r180 bottom
CN12 "PJ3028B-3" PJ3028B 348.25,2040 r180 bottom
CN13 "DF37NB-10DS-0.4V (51)" DF37NB-10DS-0R4V 556.56,1716.42 r180 bottom
CN14 "" HDR_1X4_2R54 4848.1,1580 r180 bottom
CN15 "SSW-108-22-L-S-VS" SSW-108-22-X-S-VS 2703.1,362.5 r0 bottom
CN16 "SSW-106-22-X-S-VS" SSW-106-22-X-S-VS 1903.1,362.5 r0 bottom value="Socket 6x1"
CN17 "PJS008-2003-1" MSD_PJS008_ 1035.6,315 r0 bottom
D1 "BAT60JFILM" SOD-323 4428.1,1685 r270 top
D2 "" SOD-323 3966.84,585 r270 top
D3 "BAT60JFILM" SOD-323 4042.1,585 r270 top
D4 "" SOD-323 4117.1,585 r270 top
D5 "ESDA6V1BC6" SOT23-6L 2890.89,325 r270 top
D6 "BAT60JFILM" SOD-323 686,1175 r270 bottom
H1 "POSITION HOLE" HOLE_C7D3R5 4715,195 r0 top
H2 "POSITION HOLE" HOLE_C7D3R5 175,2465 r0 top
H3 "POSITION HOLE" HOLE_C7D3R5 175,175 r0 top
H4 "POSITION HOLE" HOLE_C7D3R5 4925,2460 r0 top
JP1 "" SIP2 2883.1,2505 r180 top
JP2 "3 PIN Jumper" SIP3 3148.1,2000 r0 top
JP3 "3 PIN Jumper" SIP3 2478.1,940 r0 top
JP4 "Jumper3" SIP3 3168.1,940 r0 top
JP5 "3 PIN Jumper" SIP3 3838.1,940 r0 top
JP6 "3 PIN Jumper" SIP3 4913.1,890 r90 top
JP7 "Header M Straight 5x2H" HDR_2X5_2R54 3758.49,230 r0 top
JP8 "2 PIN Jumper" SIP2 4153.1,230 r270 top
JP9 "2 PIN Jumper" SIP2 2215,1960 r0 top
JP10 "" SIP2 3905,1230 r180 top
L1 "FCM1608KF-601T03" 0603L 2535,1905 r0 top value="600R @ 100MHz"
L2 "2.2uH" L1008_L0805_CPT 3440,615 r90 top
L3 "2.2uH" L1008_L0805_CPT 3740,615 r90 top
L4 "FCM1608KF-601T03" 0603L 2195,485 r270 top value="600R @ 100MHz"
L5 "FCM1608KF-601T03" 0603L 2490,340 r270 top value="600R @ 100MHz"
L6 "FCM1608KF-601T03" 0603L 2383.1,240 r180 top value="600R @ 100MHz"
L7 "LQH32PN4R7NN0L" 1210L 2103.1,140 r180 top value=100uH
L8 "FCM1608KF-601T03" 0603L 740,1445 r0 bottom value="600R @ 100MHz"
LD1 "19-217/S2C-AM2N2VY/3T" 0603D 1488.1,2490 r270 top value=Orange
LD2 "LED_green" 0603D 1593.1,2490 r270 top value=Green
LD3 "19-213SY6C/S530-E2/TR8LED" 0603D 1783.1,2485 r270 top value=Green
LD4 "19-217/R6C-AL1M2VY/3T" 0603D 3625,1218.1 r270 top value=RED
LD5 "HSMF-A201-A00J1" LED2_3528 4468.1,155 r180 top value=Red/Yellow-Green
LD6 "19-213SY6C/S530-E2/TR8LED" 0603D 2568.1,140 r270 top value=Green
LD7 "19-217/R6C-AL1M2VY/3T" 0603D 3308.1,140 r270 top value=RED
LD8 "19-213SY6C/S530-E2/TR8LED" 0603D 4288.1,140 r270 top value=Green
R1 "RC0603FR-07680RL" 0603R 1488.1,2345 r90 top value=680
R2 "RC0603FR-07510RL" 0603R 1593.1,2345 r90 top value=510
R4 "RC0603JR-07100RL" 0603R 4145,2165 r180 top value=100
R5 "RC0603JR-07100RL" 0603R 4305,2165 r0 top value=100
R6 "RC0603JR-0722RL" 0603R 3508.1,2130 r270 top value=22
R7 "RC0603JR-0722RL" 0603R 3558.1,2130 r270 top value=22
R8 "RC0603JR-0722RL" 0603R 3608.1,2130 r270 top value=22
R12 "0" 0603R 2235,1815 r180 top
R13 "RC0603FR-07100KL" 0603R 2048.1,1815 r180 top value=100K
R14 "RC0603FR-07100KL" 0603R 2353.1,1815 r0 top value=100K
R15 "RC0603FR-07100KL" 0603R 2353.1,1685 r180 top value=100K
R16 "RC0603JR-07100RL" 0603R 4096,1685 r270 top value=100
R17 "RC0603FR-07100KL" 0603R 4150,1685 r90 top value=100K
R18 "" 0603R 2675,1680 r90 top value=0
R20 "RC0603FR-07100KL" 0603R 3055,1680 r270 top value=100K
R21 "" 0603R 3115,1680 r270 top value=100K
R22 "RC0603FR-074K7L" 0603R 4265,1680 r270 top value=4K7
R23 "RC0603FR-072K7L" 0603R 4315,1680 r90 top value=2K7
R24 "" 0603R 4364.1,1680 r270 top value=0Ohm
R25 "RC0603JR-07100RL" 0603R 4495,1680 r270 top value=100
R26 "RC0603JR-0722RL" 0603R 3398.1,1630 r90 top value=22
R27 "RC0603FR-0710KL" 0603R 3453.1,1630 r270 top value=10K
R28 "RC0603JR-0722RL" 0603R 3510,1630 r90 top value=22
R29 "RC0603JR-0722RL" 0603R 3560,1630 r90 top value=22
R30 "RC0603FR-0710KL" 0603R 3929.1,1550 r0 top value=10K
R31 "" 0603R 3929.1,1495 r0 top value=100K
R32 "RC0603FR-0710KL" 0603R 3490,1488.1 r180 top value=10K
R33 "RC0603FR-07100KL" 0603R 4838.1,1420 r0 top value=100K
R34 "RC0603FR-0736KL" 0603R 4573.1,1400 r90 top value=36K
R35 "RC0603JR-07100RL" 0603R 4623.1,1400 r90 top value=100
R36 "820" 0603R 3625,1338.1 r90 top
R37 "RC0603FR-071K5L" 0603R 4838.1,1365 r0 top value=1K5
R41 "" 0603R 4025,1095 r90 top value=100K
R42 "RC0603FR-071K5L" 0603R 2725,1190 r90 top value=1K5
R43 "RC0603FR-071K5L" 0603R 2778.1,1190 r90 top value=1K5
R44 "RC0603FR-0710KL" 0603R 4838.1,1165 r180 top value=10K
R45 "RC0603FR-074K7L" 0603R 3965,1095 r270 top value=4K7
R46 "RC0603JR-070RL" 0603R 4095,1095 r270 top value=0
R47 "RC0603JR-070RL" 0603R 4170,1095 r90 top value=0
R48 "RC0603FR-07100KL" 0603R 4260,1095 r90 top value=100K
R49 "RC0603FR-074K7L" 0603R 3905,1095 r270 top value=4K7
R50 "RC0603FR-072K2L" 0603R 3415,1088.1 r90 top value=2K2
R51 "RC0603JR-070RL" 0603R 4665,935 r270 top value=0
R52 "RC0603FR-07100KL" 0603R 2165,791.38 r0 top value=100K
R53 "RC0603FR-07100KL" 0603R 4683.1,745 r90 top value=100K
R54 "RC0603FR-07100KL" 0603R 4738.1,745 r90 top value=100K
R55 "RC0603JR-070RL" 0603R 4793.1,745 r270 top value=0
R56 "RC0603JR-07100RL" 0603R 5015,685 r90 top value=100
R57 "RC0603JR-070RL" 0603R 3248.1,550 r90 top value=0
R58 "RC0603JR-0747KL" 0603R 3308.1,550 r270 top value=47K
R59 "RC0603JR-07100RL" 0603R 5015,560 r90 top value=100
R60 "RC0603JR-07100RL" 0603R 805,475 r180 top value=100
R62 "RC0603JR-0747KL" 0603R 2670,460 r0 top value=47K
R63 "RC0603JR-07100RL" 0603R 5015,420 r90 top value=100
R64 "RC0603JR-0747KL" 0603R 3308.1,420 r270 top value=47K
R65 "RC0603JR-0710KL" 0603R 2668.1,400 r0 top value=10K
R66 "RC0603JR-07100RL" 0603R 5010,255 r90 top value=100
R67 "RC0603FR-0710RL" 0603R 2258.1,345 r0 top value=10
R68 "820" 0603R 4288.1,315 r90 top
R69 "RC0603JR-07100RL" 0603R 4378.1,315 r270 top value=100
R70 "RC0603JR-070RL" 0603R 4438.1,315 r270 top value=0
R71 "RC0603JR-07100RL" 0603R 4540,315 r270 top value=100
R72 "1K" 0603R 3075,305 r270 top
R73 "RC0603FR-07100KL" 0603R 2258.1,290 r0 top value=100K
R74 "RC0603JR-07330RL" 0603R 2568.1,265 r270 top value=330
R75 "RC0603JR-07620RL" 0603R 3308.1,265 r270 top value=620
R76 "RC0603FR-07100KL" 0603R 1925,190 r180 top value=100K
R77 "" 0603R 1980,100 r270 top value=100K
R78 "RC0603FR-0710KL" 0603R 1298.1,2530 r0 bottom value=10K
R79 "" 0603R 1420,2490 r90 bottom value=10K
R80 "RC0603JR-070RL" 0603R 1035,2355 r270 bottom value=0
R81 "RC0603FR-07100KL" 0603R 850,2245 r180 bottom value=100K
R82 "RC0603FR-072K2L" 0603R 985,2215 r270 bottom value=2K2
R83 "RC0603FR-0710KL" 0603R 1210,2210 r270 bottom value=10K
R84 "RC0603FR-07100KL" 0603R 1735,1950 r180 bottom value=100K
R85 "1_1%_0805" 0805R 1600,1950 r180 bottom value=1
R86 "RC0603FR-0750RL" 0603R 735,1910 r180 bottom value=50
R87 "" 0603R 535,1855 r90 bottom value=1K5
R88 "" 0603R 465,1855 r270 bottom value=1K5
R89 "" 0603R 603,1851 r90 bottom value=100K
R90 "RC0603FR-0750RL" 0603R 735,1840 r180 bottom value=50
R91 "RC0603FR-0710KL" 0603R 1125,1800 r90 bottom value=10K
R92 "RC0603FR-076K04L" 0603R 1390,1666.9 r180 bottom value=6K04
R93 "RC0603JR-070RL" 0603R 3010,1645 r0 bottom value=0
R94 "RC0603FR-07100KL" 0603R 1735,1610 r0 bottom value=100K
R95 "10K_1%_0805" 0805R 1600,1610 r180 bottom value=10K
R96 "RC0603FR-076K04L" 0603R 1245,1555 r0 bottom value=6K04
R97 "RC0603FR-07300KL" 0603R 1125,1555 r180 bottom value=300K
R98 "RC0603FR-0711KL" 0603R 1005,1521.9 r180 bottom value=11K
R99 "" 0603R 875,1515 r0 bottom value=100K
R100 "RC0603JR-0722RL" 0603R 3135,1495 r180 bottom value=22
R101 "RC0603FR-07357KL" 0603R 1005,1466.9 r0 bottom value=357K
R102 "RC0603JR-07100RL" 0603R 1480,1455 r270 bottom value=100
R103 "RC0603FR-07300KL" 0603R 1415,1455 r270 bottom value=300K
R104 "" 0603R 875,1455 r0 bottom value=100K
R105 "RC0603JR-070RL" 0603R 1005,1413.1 r0 bottom value=0
R106 "RC0603FR-07100KL" 0603R 1735,1265 r180 bottom value=100K
R107 "24_1%_0805" 0805R 1600,1265 r180 bottom value=24
R109 "RC0603FR-07100KL" 0603R 785,1080 r0 bottom value=100K
R110 "RC0603FR-07100KL" 0603R 1720,945 r270 bottom value=100K
R111 "620_1%_0805" 0805R 1600,925 r180 bottom value=620
R112 "RC0603FR-07510RL" 0603R 1080,865 r270 bottom value=510
R113 "RC0603FR-0710KL" 0603R 1025,865 r270 bottom value=10K
R114 "RC0603JR-070RL" 0603R 900,865 r90 bottom value=0
R115 "RC0603FR-07100KL" 0603R 400,800 r90 bottom value=100K
R116 "RC0603FR-07100KL" 0603R 1513.1,790 r270 bottom value=100K
R117 "RC0603FR-07100KL" 0603R 1930,715 r90 bottom value=100K
R118 "47K" 0603R 1148.1,715 r90 bottom
R119 "47K" 0603R 1093.1,715 r90 bottom
R120 "47K" 0603R 1038.1,715 r90 bottom
R121 "47K" 0603R 878.1,715 r90 bottom
R122 "47K" 0603R 828.1,715 r90 bottom
R123 "RC0603JR-07510RL" 0603R 1850,2485 r90 top value=510
R124 "1M" 0603R 1780,2345 r90 top
R129 "RC0603JR-070RL" 0603R 1905,1670 r0 top value=0
R130 "" 0603R 1905,1725 r0 top value=0
SB1 "Solder Bridge ON" SB_0603 1840,2345 r90 top
SB2 "Solder Bridge OFF" SB_0603 3218.1,2195 r270 top
SB3 "Solder Bridge ON" SB_0603 3403.1,2130 r90 top
SB4 "Solder Bridge OFF" SB_0603 3738.1,2125 r90 top
SB5 "Solder Bridge OFF" SB_0603 3798.1,2125 r90 top
SB6 "Solder Bridge ON" SB_0603 3858.1,2125 r90 top
SB7 "Solder Bridge ON" SB_0603 3738.1,1980 r90 top
SB8 "Solder Bridge ON" SB_0603 3798.1,1980 r90 top
SB9 "Solder Bridge OFF" SB_0603 3858.1,1980 r90 top
SB11 "Solder Bridge OFF" SB_0603 4200,1680 r90 top
SB12 "Solder Bridge ON" SB_0603 1908.1,1615 r180 top
SB13 "Solder Bridge ON" SB_0603 4748.1,1130 r270 top
SB14 "Solder Bridge ON" SB_0603 2165,735 r180 top
SB15 "Solder Bridge OFF" SB_0603 2165,675 r180 top
SB16 "Solder Bridge ON" SB_0603 3173.1,550 r270 top
SB17 "Solder Bridge ON" SB_0603 933.1,2470 r90 bottom
SB18 "Solder Bridge ON" SB_0603 1275,2125 r180 bottom
SB19 "Solder Bridge ON" SB_0603 850,1975 r0 bottom
SB20 "Solder Bridge ON" SB_0603 740,1730 r180 bottom
SB21 "Solder Bridge ON" SB_0603 740,1570 r0 bottom
SB22 "Solder Bridge OFF" SB_0603 740,1510 r180 bottom
SB24 "Solder Bridge ON" SB_0603 1135,865 r90 bottom
SB25 "Solder Bridge OFF" SB_0603 1798.1,560 r270 bottom
SB26 "Solder Bridge ON" SB_0603 1738.1,560 r270 bottom
SB27 "Solder Bridge OFF" SB_0603 1658.1,560 r270 bottom
SB28 "Solder Bridge ON" SB_0603 1598.1,560 r270 bottom
SW1 "EDG-501S" SW1_11R7X9R7-12R2X9R65-HDR_CPT 4378.1,625 r270 top
T1 "BSN20BK" SOT-23 1685,2360 r0 top
T2 "9013-SOT23" SOT-23 4710,1400 r0 top
T3 "9013-SOT23" SOT-23 2673.1,295 r180 top
T4 "PMN30XP" SOT23-6L 1663.1,1820 r0 bottom
T5 "PMN30XP" SOT23-6L 1413.1,1820 r0 bottom
T6 "PMN30XP" SOT23-6L 1663.1,1475 r0 bottom
T7 "PMN30XP" SOT23-6L 1663.1,1135 r0 bottom
T8 "PMN30XP" SOT23-6L 1416.2,1135 r0 bottom
T9 "PMN30XP" SOT23-6L 1663.1,790 r0 bottom
T10 "PMN30XP" SOT23-6L 1413.1,790 r0 bottom
T11 "PMN30XP" SOT23-6L 543.1,790 r0 bottom
T12 "PMN30XP" SOT23-6L 298.1,790 r0 bottom
U1 "IMP34DT05TR" MP34DT01TR 472.94,2519.76 r270 top
U2 "IMP34DT05TR" MP34DT01TR 1299.63,2519.76 r270 top
U3 "MX25R6435FM2IL0" SOIC8_1R27_5R28X7R9 3532.6,1875.5 r0 top
U4 "IS66WV51216EBLL-70BLI" FBGA48_0R75_6X8 2133.1,1550 r0 top
U5 "STM32L496AG" FBGA169_0R5_7X7 2878.1,1425 r270 top
U6 "STM32F103CBT6" LQFP48_0R5_9X9 4224.1,1385 r0 top
U7 "ST890CDR" SOIC8_1R27_4R9X6 3490,1298.1 r180 top
U8 "SN74LVC2T45DCUT" USOP8_0R5_2X3R1 4763.1,988 r180 top
U9 "LD3985M33R" SOT23-5 4375,980 r270 top
U10 "LD1117S50TR" SOT-223 2573.1,625 r180 top
U11 "SN74LVC2T45DCUT" USOP8_0R5_2X3R1 4733.1,585 r180 top
U12 "TPS62743" BGA8_0R4_0R9X1R6 3570,565 r180 bottom
U13 "TPS62743" BGA8_0R4_0R9X1R6 3847,568 r180 bottom
U14 "STMPS2141STR" SOT23-5 3213.1,405 r0 top
U15 "STLD40DPUR" SON8_0R65_3X3 2093.1,294 r90 top
U16 "MP23DB01MMTR" RHLGA5LD 1297.29,2390 r90 bottom value=MP23DB01HPTR
U17 "MP23DB01MMTR" RHLGA5LD 470.6,2390 r90 bottom value=MP23DB01HPTR
U18 "CS42L51-CNZ" QFN32_0R5_5X5 1065,2010 r270 bottom
U19 "TSZ122IST" MINISO8 1200,1651.9 r270 bottom
U20 "TSZ122IST" MINISO8 1200,1456.9 r270 bottom
U21 "STM32L152CCT6" LQFP48_0R5_9X9 1070,1150 r0 bottom
U22 "USBLC6-2SC6" SOT23-6L 4760,1260 r90 top
U23 "ST1PS01EJR" BGA8_0R312-0R25_1R11X1R41 3578.1,565 r180 top
U24 "ST1PS01EJR" BGA8_0R312-0R25_1R11X1R41 3853.1,565 r180 top
X1 "NDK NX3215SA-32.768KHZ-EXS00A-MU00525" XTAL_2SM_3R2X1R5 2887.6,1819 r180 top
X2 "NX3225GD-8.00M" XTAL_2SM_3R2X2R5 3793,1380 r90 top
Z1 "STPS1L40M" DO-216AA 1928.1,325 r270 top

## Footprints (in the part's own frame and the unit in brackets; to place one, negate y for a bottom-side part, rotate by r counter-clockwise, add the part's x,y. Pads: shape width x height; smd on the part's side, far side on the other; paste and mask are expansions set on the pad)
0402C [mil] "0402C"
  rect 22x22 smd: 1(-20,0) 2(20,0)
  silkscreen extent -40,-20 40,20, body extent -35,-14 35,14, height 150
0603C [mil] "0603C"
  rect 35x32 smd: 1(-30,0) 2(30,0)
  TOP pour cut-out: -5,-10 5,-10 5,10 -5,10 -5,-10
  silkscreen extent -57,-25 57,25
0603D [mil] "0603D"
  rect 35x32 smd: 1(-30,0) 2(30,0)
  TOP pour cut-out: -5,-10 5,-10 5,10 -5,10 -5,-10
  silkscreen extent -57,-25 65,25, body extent -50,-20 50,20, height 150
0603L [mil] "0603L"
  rect 35x32 smd: 1(-30,0) 2(30,0)
  silkscreen extent -60,-28 60,28, body extent -50,-19 50,19, height 150
0603R [mil] "0603R"
  rect 31x32 smd: 1(-30,0) 2(30,0)
  TOP pour cut-out: -5,10 -5,-10 5,-10 5,10 -5,10
  silkscreen extent -57,-25 57,25, body extent -50,-20 50,20, height 150
0805R [mil] "0805R"
  rect 40x50 smd: 1(35,0) 2(-35,0)
  silkscreen extent -70,-35 71,35, body extent -65,-25 65,25, height 150
1206C [mil] "1206C"
  rect 46x60 smd: 1(-58,0) 2(58,0)
  silkscreen extent -91,-40 91,40, body extent -81,-30 81,30, height 150
1210L [mil] "1210L"
  rect 46x100 smd: 1(-58,0) 2(58,0)
  silkscreen extent -91,-60 91,60, body extent -83,-53 83,53, height 150
BGA8_0R4_0R9X1R6 [mil] "BGA8_0R4_0R9X1R6"
  round 10 smd: A1(7.87,-23.62) A2(-7.87,-23.62) B1(7.87,-7.87) B2(-7.87,-7.87) C1(7.87,7.87) C2(-7.87,7.87) D1(7.87,23.62) D2(-7.87,23.62)
  silkscreen extent -20,-37 22,35, body extent -20,-35 20,35, height 150
BGA8_0R312-0R25_1R11X1R41 [mil] "BGA8_0R312-0R25_1R11X1R41"
  round 9 smd mask+1: A1(-12.28,19.69) A3(12.28,19.69) B2(0,9.84) C1(-12.28,0) C3(12.28,0) D2(0,-9.84) E1(-12.28,-19.69) E3(12.28,-19.69)
  silkscreen extent -30,-30 25,35, body extent -22,-28 22,28, height 150
DF37NB-10DS-0R4V [mil] "DF37NB-10DS-0R4V"
  rect 8x27 smd: 1(-31.82,52.17) 2(-16.07,52.17) 3(-0.32,52.17) 4(15.43,52.17) 5(31.18,52.17) 6(31.18,-52.17) 7(15.43,-52.17) 8(-0.32,-52.17) 9(-16.07,-52.17) 10(-31.82,-52.17)
  rect 16x43 smd: 11(79.99,0) 12(-80.63,0)
  silkscreen extent -83,-46 83,79, body extent -90,-70 90,70, height 150
DO-216AA [mil] "DO-216AA"
  rect 45x32 smd: 1(65,0)
  rect 90x89 smd: 2(-25,0)
  silkscreen extent -105,-60 105,60, body extent -100,-55 100,55, height 150
FBGA48_0R75_6X8 [mil] "FBGA48_0R75_6X8"
  round 14 smd mask+2: A1(-73.82,103.35) A2(-44.29,103.35) A3(-14.76,103.35) A4(14.76,103.35) A5(44.29,103.35) A6(73.82,103.35) B1(-73.82,73.82) B2(-44.29,73.82) B3(-14.76,73.82) B4(14.76,73.82) B5(44.29,73.82) B6(73.82,73.82) C1(-73.82,44.29) C2(-44.29,44.29) C3(-14.76,44.29) C4(14.76,44.29) C5(44.29,44.29) C6(73.82,44.29) D1(-73.82,14.76) D2(-44.29,14.76) D3(-14.76,14.76) D4(14.76,14.76) D5(44.29,14.76) D6(73.82,14.76) E1(-73.82,-14.76) E2(-44.29,-14.76) E3(-14.76,-14.76) E4(14.76,-14.76) E5(44.29,-14.76) E6(73.82,-14.76) F1(-73.82,-44.29) F2(-44.29,-44.29) F3(-14.76,-44.29) F4(14.76,-44.29) F5(44.29,-44.29) F6(73.82,-44.29) G1(-73.82,-73.82) G2(-44.29,-73.82) G3(-14.76,-73.82) G4(14.76,-73.82) G5(44.29,-73.82) G6(73.82,-73.82) H1(-73.82,-103.35) H2(-44.29,-103.35) H3(-14.76,-103.35) H4(14.76,-103.35) H5(44.29,-103.35) H6(73.82,-103.35)
  silkscreen extent -197,-236 197,236, body extent -120,-160 120,160, height 150
FBGA169_0R5_7X7 [mil] "FBGA169_0R5_7X7"
  round 11 smd mask+2: A1(-118.11,118.11) A2(-98.43,118.11) A3(-78.74,118.11) A4(-59.06,118.11) A5(-39.37,118.11) A6(-19.69,118.11) A7(0,118.11) A8(19.69,118.11) A9(39.37,118.11) A10(59.06,118.11) A11(78.74,118.11) A12(98.43,118.11) A13(118.11,118.11) B1(-118.11,98.43) B2(-98.43,98.43) B3(-78.74,98.43) B4(-59.06,98.43) B5(-39.37,98.43) B6(-19.69,98.43) B7(0,98.43) B8(19.69,98.43) B9(39.37,98.43) B10(59.06,98.43) B11(78.74,98.43) B12(98.43,98.43) B13(118.11,98.43) C1(-118.11,78.74) C2(-98.43,78.74) C3(-78.74,78.74) C4(-59.06,78.74) C5(-39.37,78.74) C6(-19.69,78.74) C7(0,78.74) C8(19.69,78.74) C9(39.37,78.74) C10(59.06,78.74) C11(78.74,78.74) C12(98.43,78.74) C13(118.11,78.74) D1(-118.11,59.06) D2(-98.43,59.06) D3(-78.74,59.06) D4(-59.06,59.06) D5(-39.37,59.06) D6(-19.69,59.06) D7(0,59.06) D8(19.69,59.06) D9(39.37,59.06) D10(59.06,59.06) D11(78.74,59.06) D12(98.43,59.06) D13(118.11,59.06) E1(-118.11,39.37) E2(-98.43,39.37) E3(-78.74,39.37) E4(-59.06,39.37) E5(-39.37,39.37) E6(-19.69,39.37) E7(0,39.37) E8(19.69,39.37) E9(39.37,39.37) E10(59.06,39.37) E11(78.74,39.37) E12(98.43,39.37) E13(118.11,39.37) F1(-118.11,19.69) F2(-98.43,19.69) F3(-78.74,19.69) F4(-59.06,19.69) F5(-39.37,19.69) F6(-19.69,19.69) F7(0,19.69) F8(19.69,19.69) F9(39.37,19.69) F10(59.06,19.69) F11(78.74,19.69) F12(98.43,19.69) F13(118.11,19.69) G1(-118.11,0) G2(-98.43,0) G3(-78.74,0) G4(-59.06,0) G5(-39.37,0) G6(-19.69,0) G7(0,0) G8(19.69,0) G9(39.37,0) G10(59.06,0) G11(78.74,0) G12(98.43,0) G13(118.11,0) H1(-118.11,-19.69) H2(-98.43,-19.69) H3(-78.74,-19.69) H4(-59.06,-19.69) H5(-39.37,-19.69) H6(-19.69,-19.69) H7(0,-19.69) H8(19.69,-19.69) H9(39.37,-19.69) H10(59.06,-19.69) H11(78.74,-19.69) H12(98.43,-19.69) H13(118.11,-19.69) J1(-118.11,-39.37) J2(-98.43,-39.37) J3(-78.74,-39.37) J4(-59.06,-39.37) J5(-39.37,-39.37) J6(-19.69,-39.37) J7(0,-39.37) J8(19.69,-39.37) J9(39.37,-39.37) J10(59.06,-39.37) J11(78.74,-39.37) J12(98.43,-39.37) J13(118.11,-39.37) K1(-118.11,-59.06) K2(-98.43,-59.06) K3(-78.74,-59.06) K4(-59.06,-59.06) K5(-39.37,-59.06) K6(-19.69,-59.06) K7(0,-59.06) K8(19.69,-59.06) K9(39.37,-59.06) K10(59.06,-59.06) K11(78.74,-59.06) K12(98.43,-59.06) K13(118.11,-59.06) L1(-118.11,-78.74) L2(-98.43,-78.74) L3(-78.74,-78.74) L4(-59.06,-78.74) L5(-39.37,-78.74) L6(-19.69,-78.74) L7(0,-78.74) L8(19.69,-78.74) L9(39.37,-78.74) L10(59.06,-78.74) L11(78.74,-78.74) L12(98.43,-78.74) L13(118.11,-78.74) M1(-118.11,-98.43) M2(-98.43,-98.43) M3(-78.74,-98.43) M4(-59.06,-98.43) M5(-39.37,-98.43) M6(-19.69,-98.43) M7(0,-98.43) M8(19.69,-98.43) M9(39.37,-98.43) M10(59.06,-98.43) M11(78.74,-98.43) M12(98.43,-98.43) M13(118.11,-98.43) N1(-118.11,-118.11) N2(-98.43,-118.11) N3(-78.74,-118.11) N4(-59.06,-118.11) N5(-39.37,-118.11) N6(-19.69,-118.11) N7(0,-118.11) N8(19.69,-118.11) N9(39.37,-118.11) N10(59.06,-118.11) N11(78.74,-118.11) N12(98.43,-118.11) N13(118.11,-118.11)
  silkscreen extent -256,-256 256,256, body extent -138,-138 138,138, height 150
FH26-29S-0R3SHW [mil] "FH26-29S-0R3SHW"
  rect 12x32 smd: 1(-164.05,-59.59) 3(-140.43,-59.59) 5(-116.81,-59.59) 7(-93.19,-59.59) 9(-69.57,-59.59) 11(-45.94,-59.59) 13(-22.32,-59.59) 15(1.3,-59.59) 17(24.92,-59.59) 19(48.54,-59.59) 21(72.17,-59.59) 23(95.79,-59.59) 25(119.41,-59.59) 27(143.03,-59.59) 29(166.65,-59.59)
  rect 11x32 smd mask+2: 2(-152.24,54.59) 4(-128.62,54.59) 6(-105,54.59) 8(-81.38,54.59) 10(-57.76,54.59) 12(-34.13,54.59) 14(-10.51,54.59) 16(13.11,54.59) 18(36.73,54.59) 20(60.36,54.59) 22(83.98,54.59) 24(107.6,54.59) 26(131.22,54.59) 28(154.84,54.59)
  rect 16x37 smd: " "(-191.61,-49.74) " "(194.21,-49.74)
  silkscreen extent -202,-120 207,65, body extent -204,-75 204,75, height 150
FPU330ZH-BT1D3-CA [mil] "FPU330ZH-BT1D3-CA"
  rect 11x49 smd mask+2: 1(-285,92.5) 2(-265.31,92.5) 3(-245.63,92.5) 4(-225.94,92.5) 5(-206.26,92.5) 6(-186.57,92.5) 7(-166.89,92.5) 8(-147.2,92.5) 9(-127.52,92.5) 10(-107.83,92.5) 11(-88.15,92.5) 12(-68.46,92.5) 13(-48.78,92.5) 14(-29.09,92.5) 15(-9.41,92.5) 16(10.28,92.5) 17(29.96,92.5) 18(49.65,92.5) 19(69.33,92.5) 20(89.02,92.5) 21(108.7,92.5) 22(128.39,92.5) 23(148.07,92.5) 24(167.76,92.5) 25(187.44,92.5) 26(207.13,92.5) 27(226.81,92.5) 28(246.5,92.5) 29(266.18,92.5) 30(285.87,92.5)
  rect 79x98 smd: 31(-351.54,-8.88) 32(352.4,-8.88)
  silkscreen extent -381,-123 382,158, body extent -395,-123 395,123, height 150
HDR_1X4_2R54 [mil] "HDR_1X4_2R54"
  rect 52x52 hole 36: 1(150,0)
  round 52 hole 36: 2(50,0) 3(-50,0) 4(-150,0)
  silkscreen extent -205,-55 220,70, body extent -200,-50 200,50, height 150
HDR_1X6_2R54_W [mil] "HDR_1X6_2R54_W"
  rect 60x60 / inner round 60 / far side rect 60x60 hole 40: 1(-250,0)
  round 60 hole 40: 2(-150,0) 3(-50,0) 4(50,0) 5(150,0) 6(250,0)
  silkscreen extent -315,-65 300,50, body extent -300,-50 300,50, height 150
HDR_2X5_2R54 [mil] "HDR_2X5_2R54"
  rect 52x52 hole 36: 1(-200.39,-50)
  round 52 hole 36: 2(-200.39,50) 3(-100.39,-50) 4(-100.39,50) 5(-0.39,-50) 6(-0.39,50) 7(99.61,-50) 8(99.61,50) 9(199.61,-50) 10(199.61,50)
  silkscreen extent -265,-120 250,105, body extent -245,-100 245,100, height 150
HOLE_C7D3R5 [mil] "HOLE_C7D3R5"
  round 276 hole 138: 1(0,0)
  body extent -144,-144 144,144, height 150
L1008_L0805_CPT [mil] "L1008_L0805_CPT"
  rect 53x100 smd: 1(-39,0) 2(39,0)
  silkscreen extent -80,-65 80,65, body extent -70,-55 70,55, height 150
LED2_3528 [mil] "LED2_3528"
  rect 44x59 smd: 1(-29.53,-59.06) 2(-29.53,59.06) 3(29.53,59.06) 4(29.53,-59.06)
  silkscreen extent -100,-70 65,69, body extent -55,-90 55,90, height 150
LQFP48_0R5_9X9 [mil] "LQFP48_0R5_9X9"
  rect 53x11 smd mask+2: 1(-171.26,108.27) 2(-171.26,88.58) 3(-171.26,68.9) 4(-171.26,49.21) 5(-171.26,29.53) 6(-171.26,9.84) 7(-171.26,-9.84) 8(-171.26,-29.53) 9(-171.26,-49.21) 10(-171.26,-68.9) 11(-171.26,-88.58) 12(-171.26,-108.27) 25(171.26,-108.27) 26(171.26,-88.58) 27(171.26,-68.9) 28(171.26,-49.21) 29(171.26,-29.53) 30(171.26,-9.84) 31(171.26,9.84) 32(171.26,29.53) 33(171.26,49.21) 34(171.26,68.9) 35(171.26,88.58) 36(171.26,108.27)
  rect 11x53 smd mask+2: 13(-108.27,-171.26) 14(-88.58,-171.26) 15(-68.9,-171.26) 16(-49.21,-171.26) 17(-29.53,-171.26) 18(-9.84,-171.26) 19(9.84,-171.26) 20(29.53,-171.26) 21(49.21,-171.26) 22(68.9,-171.26) 23(88.58,-171.26) 24(108.27,-171.26) 37(108.27,171.26) 38(88.58,171.26) 39(68.9,171.26) 40(49.21,171.26) 41(29.53,171.26) 42(9.84,171.26) 43(-9.84,171.26) 44(-29.53,171.26) 45(-49.21,171.26) 46(-68.9,171.26) 47(-88.58,171.26) 48(-108.27,171.26)
  silkscreen extent -230,-220 220,220
MICRO_USB_B_105017 [mil] "MICRO_USB_B_105017"
  rect 16x53 smd: 1(-51.18,85.45) 2(-25.59,85.45) 3(0,85.45) 4(25.59,85.45) 5(51.18,85.45)
  oval 47x75 hole 24 slot 51 at 90 deg: 6(-137.8,-19.86) 7(137.8,-19.86)
  round 59 hole 33: 8(-98.43,86.44) 9(98.43,86.44)
  rect 59x75 smd: 10(-39.37,-19.86) 11(39.37,-19.86)
  TOP region: 161.42,-37.58 161.42,-2.15 161.42,-2.15 161.35,-0.43 161.12,1.27 160.75,2.95 160.23,4.58 159.58,6.17 158.78,7.69 157.86,9.14 156.81,10.51 155.65,11.77 154.39,12.93 153.02,13.98 151.58,14.9 150.05,15.7 148.46,16.35 146.83,16.87 145.15,17.24 143.45,17.47 141.73,17.54 90.55,17.54 90.55,-57.26 141.73,-57.26 141.73,-57.26 143.45,-57.19 145.15,-56.96 146.82,-56.59 148.46,-56.08 150.05,-55.42 151.57,-54.63 153.02,-53.71 154.38,-52.66 155.65,-51.5 156.81,-50.24 157.86,-48.88 158.78,-47.43 159.57,-45.91 160.23,-44.32 160.75,-42.68 161.12,-41.01 161.34,-39.31 161.42,-37.59 161.42,-37.58
  TOP region: -161.42,-2.15 -161.42,-37.58 -161.42,-37.58 -161.35,-39.3 -161.12,-41 -160.75,-42.67 -160.23,-44.31 -159.58,-45.9 -158.78,-47.42 -157.86,-48.87 -156.82,-50.23 -155.66,-51.5 -154.39,-52.66 -153.03,-53.7 -151.58,-54.62 -150.06,-55.42 -148.47,-56.07 -146.83,-56.59 -145.16,-56.96 -143.46,-57.19 -141.74,-57.26 -141.73,-57.26 -90.55,-57.26 -90.55,17.54 -141.73,17.54 -141.73,17.54 -143.45,17.47 -145.15,17.24 -146.83,16.87 -148.46,16.35 -150.05,15.7 -151.58,14.9 -153.02,13.98 -154.39,12.93 -155.65,11.77 -156.81,10.51 -157.86,9.14 -158.78,7.69 -159.58,6.17 -160.23,4.58 -160.75,2.95 -161.12,1.27 -161.35,-0.43 -161.42,-2.15
  silkscreen extent -148,-116 148,143, body extent -165,-118 165,118, height 150
MINISO8 [mil] "MINISO8"
  rect 14x47 smd: 1(38.39,87.99) 2(12.8,87.99) 3(-12.8,87.99) 4(-38.39,87.99) 5(-38.39,-87.99) 6(-12.8,-87.99) 7(12.8,-87.99) 8(38.39,-87.99)
  silkscreen extent -65,-45 83,139, body extent -59,-115 59,115, height 150
MOLEX_47590001 [mil] "MOLEX_47590001"
  rect 16x53 smd: 1(51.18,85.06) 2(25.59,85.06) 3(0,85.06) 4(-25.59,85.06) 5(-51.18,85.06)
  oval 42x63 hole 30 slot 33 at 90 deg: 6(89.57,97.86) 7(-89.57,97.86)
  oval 55x75 hole 33 slot 59 at 90 deg: 8(-163.39,-27.34) 9(163.39,-27.34)
  rect 114x79 smd: 10(0,-20.25)
  silkscreen extent -161,-131 161,151, body extent -190,-130 190,130, height 150
MP34DT01TR [mil] "MP34DT01TR"
  rect 20x42 smd: 1(-16.97,26.73) 2(-16.97,-26.41) 3(16.49,-26.41) 4(16.49,26.73)
  round 6 smd: 5(-1.24,-68.84)
  TOP region: -25.83,-60.95 -25.83,-74.73 25.35,-74.73 25.35,-60.95 -25.83,-60.95
  TOP region: -55.13,45.44 -55.13,-45.12 -41.35,-45.12 -41.35,45.44 -55.13,45.44
  TOP region: -25.83,75.05 -25.83,61.27 25.35,61.27 25.35,75.05 -25.83,75.05
  TOP region: 40.87,45.44 40.87,-45.12 54.65,-45.12 54.65,45.44 40.87,45.44
  silkscreen extent -70,-80 60,90, body extent -59,-79 59,79, height 150
MSD_PJS008_ [mil] "MSD_PJS008_"
  rect 32x63 smd: 1(99.43,-278.35) 2(56.12,-278.35) 3(12.81,-278.35) 4(-30.49,-278.35) 5(-73.8,-278.35) 6(-117.11,-278.35) 7(-160.41,-278.35) 8(-203.72,-278.35)
  rect 33x63 smd: 9(-249,-278.35)
  rect 77x75 smd: 10(-284.43,123.23)
  rect 60x121 smd: 11(-293.29,239.37)
  rect 55x135 smd: 12(295.41,239.65)
  rect 63x138 smd: 13(291.36,-193.7)
  rect 47x122 smd: 14(-299.19,-213.39)
  round 28 hole 28 unplated: " "(-139.74,-50) " "(157.5,-50)
  Multi-Layer pour cut-out: 128.48,-50 130.69,-61.11 136.98,-70.52 146.39,-76.81 157.5,-79.02 157.5,-79.02 168.61,-76.81 178.02,-70.52 184.31,-61.11 186.52,-50 186.52,-50 184.31,-38.89 178.02,-29.48 168.61,-23.19 157.5,-20.98 157.5,-20.98 146.39,-23.19 136.98,-29.48 130.69,-38.89 128.48,-50
  Multi-Layer pour cut-out: -168.76,-50 -166.55,-61.11 -160.26,-70.52 -150.85,-76.81 -139.74,-79.02 -139.74,-79.02 -128.63,-76.81 -119.22,-70.52 -112.93,-61.11 -110.72,-50 -110.72,-50 -112.93,-38.89 -119.22,-29.48 -128.63,-23.19 -139.74,-20.98 -139.74,-20.98 -150.85,-23.19 -160.26,-29.48 -166.55,-38.89 -168.76,-50
  silkscreen extent -292,-341 308,315, body extent -328,-315 328,315, height 150
MT-008A [mil] "MT-008A"
  rect 39.99x70 smd: 1(-58.87,-123.3) 2(-3.75,-123.29) 3(51.37,-123.3) 4(51.37,120.81) 5(-3.75,120.8) 6(-58.87,120.81) 7(-145.48,-1.24) 8(141.92,-1.24)
  round 28 hole 28 unplated: " "(-78.55,-1.24)
  round 39 hole 39 unplated: " "(71.05,-1.24)
  Multi-Layer pour cut-out: 35.61,-1.24 38.31,-14.81 45.99,-26.3 57.49,-33.99 71.05,-36.68 71.05,-36.68 84.61,-33.99 96.11,-26.3 103.79,-14.81 106.49,-1.24 106.49,-1.24 103.79,12.32 96.11,23.82 84.61,31.5 71.05,34.2 71.05,34.2 57.49,31.5 45.99,23.82 38.31,12.32 35.61,-1.24
  Multi-Layer pour cut-out: -78.55,-30.76 -89.84,-28.52 -99.42,-22.12 -105.82,-12.54 -108.07,-1.24 -108.07,-1.24 -105.82,10.05 -99.42,19.63 -89.84,26.03 -78.55,28.28 -78.55,28.28 -67.25,26.03 -57.67,19.63 -51.27,10.05 -49.03,-1.24 -49.03,-1.24 -51.27,-12.54 -57.67,-22.12 -67.25,-28.52 -78.55,-30.76
  silkscreen extent -145,-207 142,148, body extent -169,-161 166,159, height 150
PB10 [mil] "PB10"
  rect 60x40 smd paste+12: 1(-177.16,-87.5) 2(-177.16,87.5) 3(177.18,87.5) 4(177.18,-87.5)
  silkscreen extent -125,-125 125,125, body extent -207,-108 207,108, height 150
PJ3028B [mil] "PJ3028B"
  rect 48x98 smd: 2(301.79,157.48) 7(226.99,-157.48)
  rect 79x98 smd: 3(187.62,157.48) 4(116.75,-157.48) 6(-174.58,157.48)
  rect 98x79 smd: 5(-334.03,-31.5)
  round 79 hole 79 unplated: " "(-127.34,0) " "(148.25,0)
  Multi-Layer pour cut-out: -127.34,-54.33 -148.13,-50.19 -165.76,-38.42 -177.53,-20.79 -181.67,0 -181.67,0 -177.53,20.79 -165.76,38.42 -148.13,50.19 -127.34,54.33 -127.34,54.33 -106.55,50.19 -88.92,38.42 -77.15,20.79 -73.01,0 -73.01,0 -77.15,-20.79 -88.92,-38.42 -106.55,-50.19 -127.34,-54.33
  Multi-Layer pour cut-out: 148.25,-54.33 127.46,-50.19 109.83,-38.42 98.06,-20.79 93.92,0 93.92,0 98.06,20.79 109.83,38.42 127.46,50.19 148.25,54.33 148.25,54.33 169.04,50.19 186.67,38.42 198.44,20.79 202.58,0 202.58,0 198.44,-20.79 186.67,-38.42 169.04,-50.19 148.25,-54.33
  silkscreen extent -285,-118 384,118, body extent -383,-210 383,210, height 150
QFN32_0R5_5X5 [mil] "QFN32_0R5_5X5"
  oval 34x11 smd mask+2: 1(95.28,-68.9) 2(95.28,-49.21) 3(95.28,-29.53) 4(95.28,-9.84) 5(95.28,9.84) 6(95.28,29.53) 7(95.28,49.21) 8(95.28,68.9) 17(-95.28,68.9) 18(-95.28,49.21) 19(-95.28,29.53) 20(-95.28,9.84) 21(-95.28,-9.84) 22(-95.28,-29.53) 23(-95.28,-49.21) 24(-95.28,-68.9)
  oval 11x34 smd mask+2: 9(68.9,95.28) 10(49.21,95.28) 11(29.53,95.28) 12(9.84,95.28) 13(-9.84,95.28) 14(-29.53,95.28) 15(-49.21,95.28) 16(-68.9,95.28) 25(-68.9,-95.28) 26(-49.21,-95.28) 27(-29.53,-95.28) 28(-9.84,-95.28) 29(9.84,-95.28) 30(29.53,-95.28) 31(49.21,-95.28) 32(68.9,-95.28)
  rect 135x135 smd: 33(0,0)
  silkscreen extent -105,-110 144,105, body extent -115,-115 115,115, height 150
RHLGA5LD [mil] "RHLGA5LD"
  rect 23x30 smd: 1(53.7,35.47) 2(21.34,35.47) 4(21.34,-30.47) 5(53.7,-30.47)
  round 6 smd: 3(-28,-23.5)
  round 20 hole 20: " "(-27.95,2.5)
  Multi-Layer pour cut-out: -39,-15 -45.98,-8.15 -49.13,1.11 -47.77,10.79 -42.19,18.82 -33.59,23.48 -23.82,23.76 -14.96,19.61 -8.93,11.91 -7.01,2.32 -7.01,2.32 -8.77,-6.39 -14.06,-13.53 -21.87,-17.76 -30.74,-18.29 -39,-15
  silkscreen extent -75,-58 75,63, body extent -70,-53 70,53, height 150
SB_0603 [mil] "SB_0603"
  round 6 smd: 1(-30,0) 2(30,0)
  TOP region: 50,20 50,-20 13.75,-20 -6.25,0 13.75,20 50,20
  TOP region: -50,-20 3.75,-20 -10.75,-5.5 -16.32,0.08 3.6,20 -50,20 -50,-20
  silkscreen extent -57,-25 57,25, body extent -50,-20 50,20, height 150
SIP2 [mil] "SIP2"
  rect 60x60 / inner round 60 / far side rect 60x60 hole 40: 1(-50,0)
  round 60 hole 40: 2(50,0)
  silkscreen extent -125,-50 100,50
SIP3 [mil] "SIP3"
  rect 60x60 / inner round 60 / far side rect 60x60 hole 40: 1(-100,0)
  round 60 hole 40: 2(0,0) 3(100,0)
  silkscreen extent -175,-50 150,50
SOD-323 [mil] "SOD-323"
  rect 32x32 smd: 1(44.29,1) 2(-44.29,1)
  silkscreen extent -50,-34 50,36, body extent -65,-26 65,26, height 150
SOIC8_1R27_4R9X6 [mil] "SOIC8_1R27_4R9X6"
  rect 22x70 smd: 1(-75,-103.3) 2(-25,-103.3) 3(25,-103.3) 4(75,-103.3) 5(75,103.3) 6(25,103.3) 7(-25,103.3) 8(-75,103.3)
  silkscreen extent -100,-172 100,55, body extent -96,-141 96,141, height 150
SOIC8_1R27_5R28X7R9 [mil] "SOIC8_1R27_5R28X7R9"
  rect 24x64 smd: 1(-74.5,-143.22) 2(-24.5,-143.22) 3(25.5,-143.22) 4(75.5,-143.22) 5(75.5,142.22) 6(25.5,142.22) 7(-24.5,142.22) 8(-74.5,142.22)
  silkscreen extent -125,-151 106,94, body extent -104,-178 104,178, height 150
SON8_0R65_3X3 [mil] "SON8_0R65_3X3"
  rect 16x31 smd: 1(-38.39,-58.07) 2(-12.8,-58.07) 3(12.8,-58.07) 4(38.39,-58.07) 5(38.39,58.07) 6(12.8,58.07) 7(-12.8,58.07) 8(-38.39,58.07)
  oct 1x1 smd: 9(0,0)
  silkscreen extent -65,-113 65,65, body extent -78,-78 78,78, height 150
